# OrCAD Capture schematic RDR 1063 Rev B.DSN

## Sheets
1 6
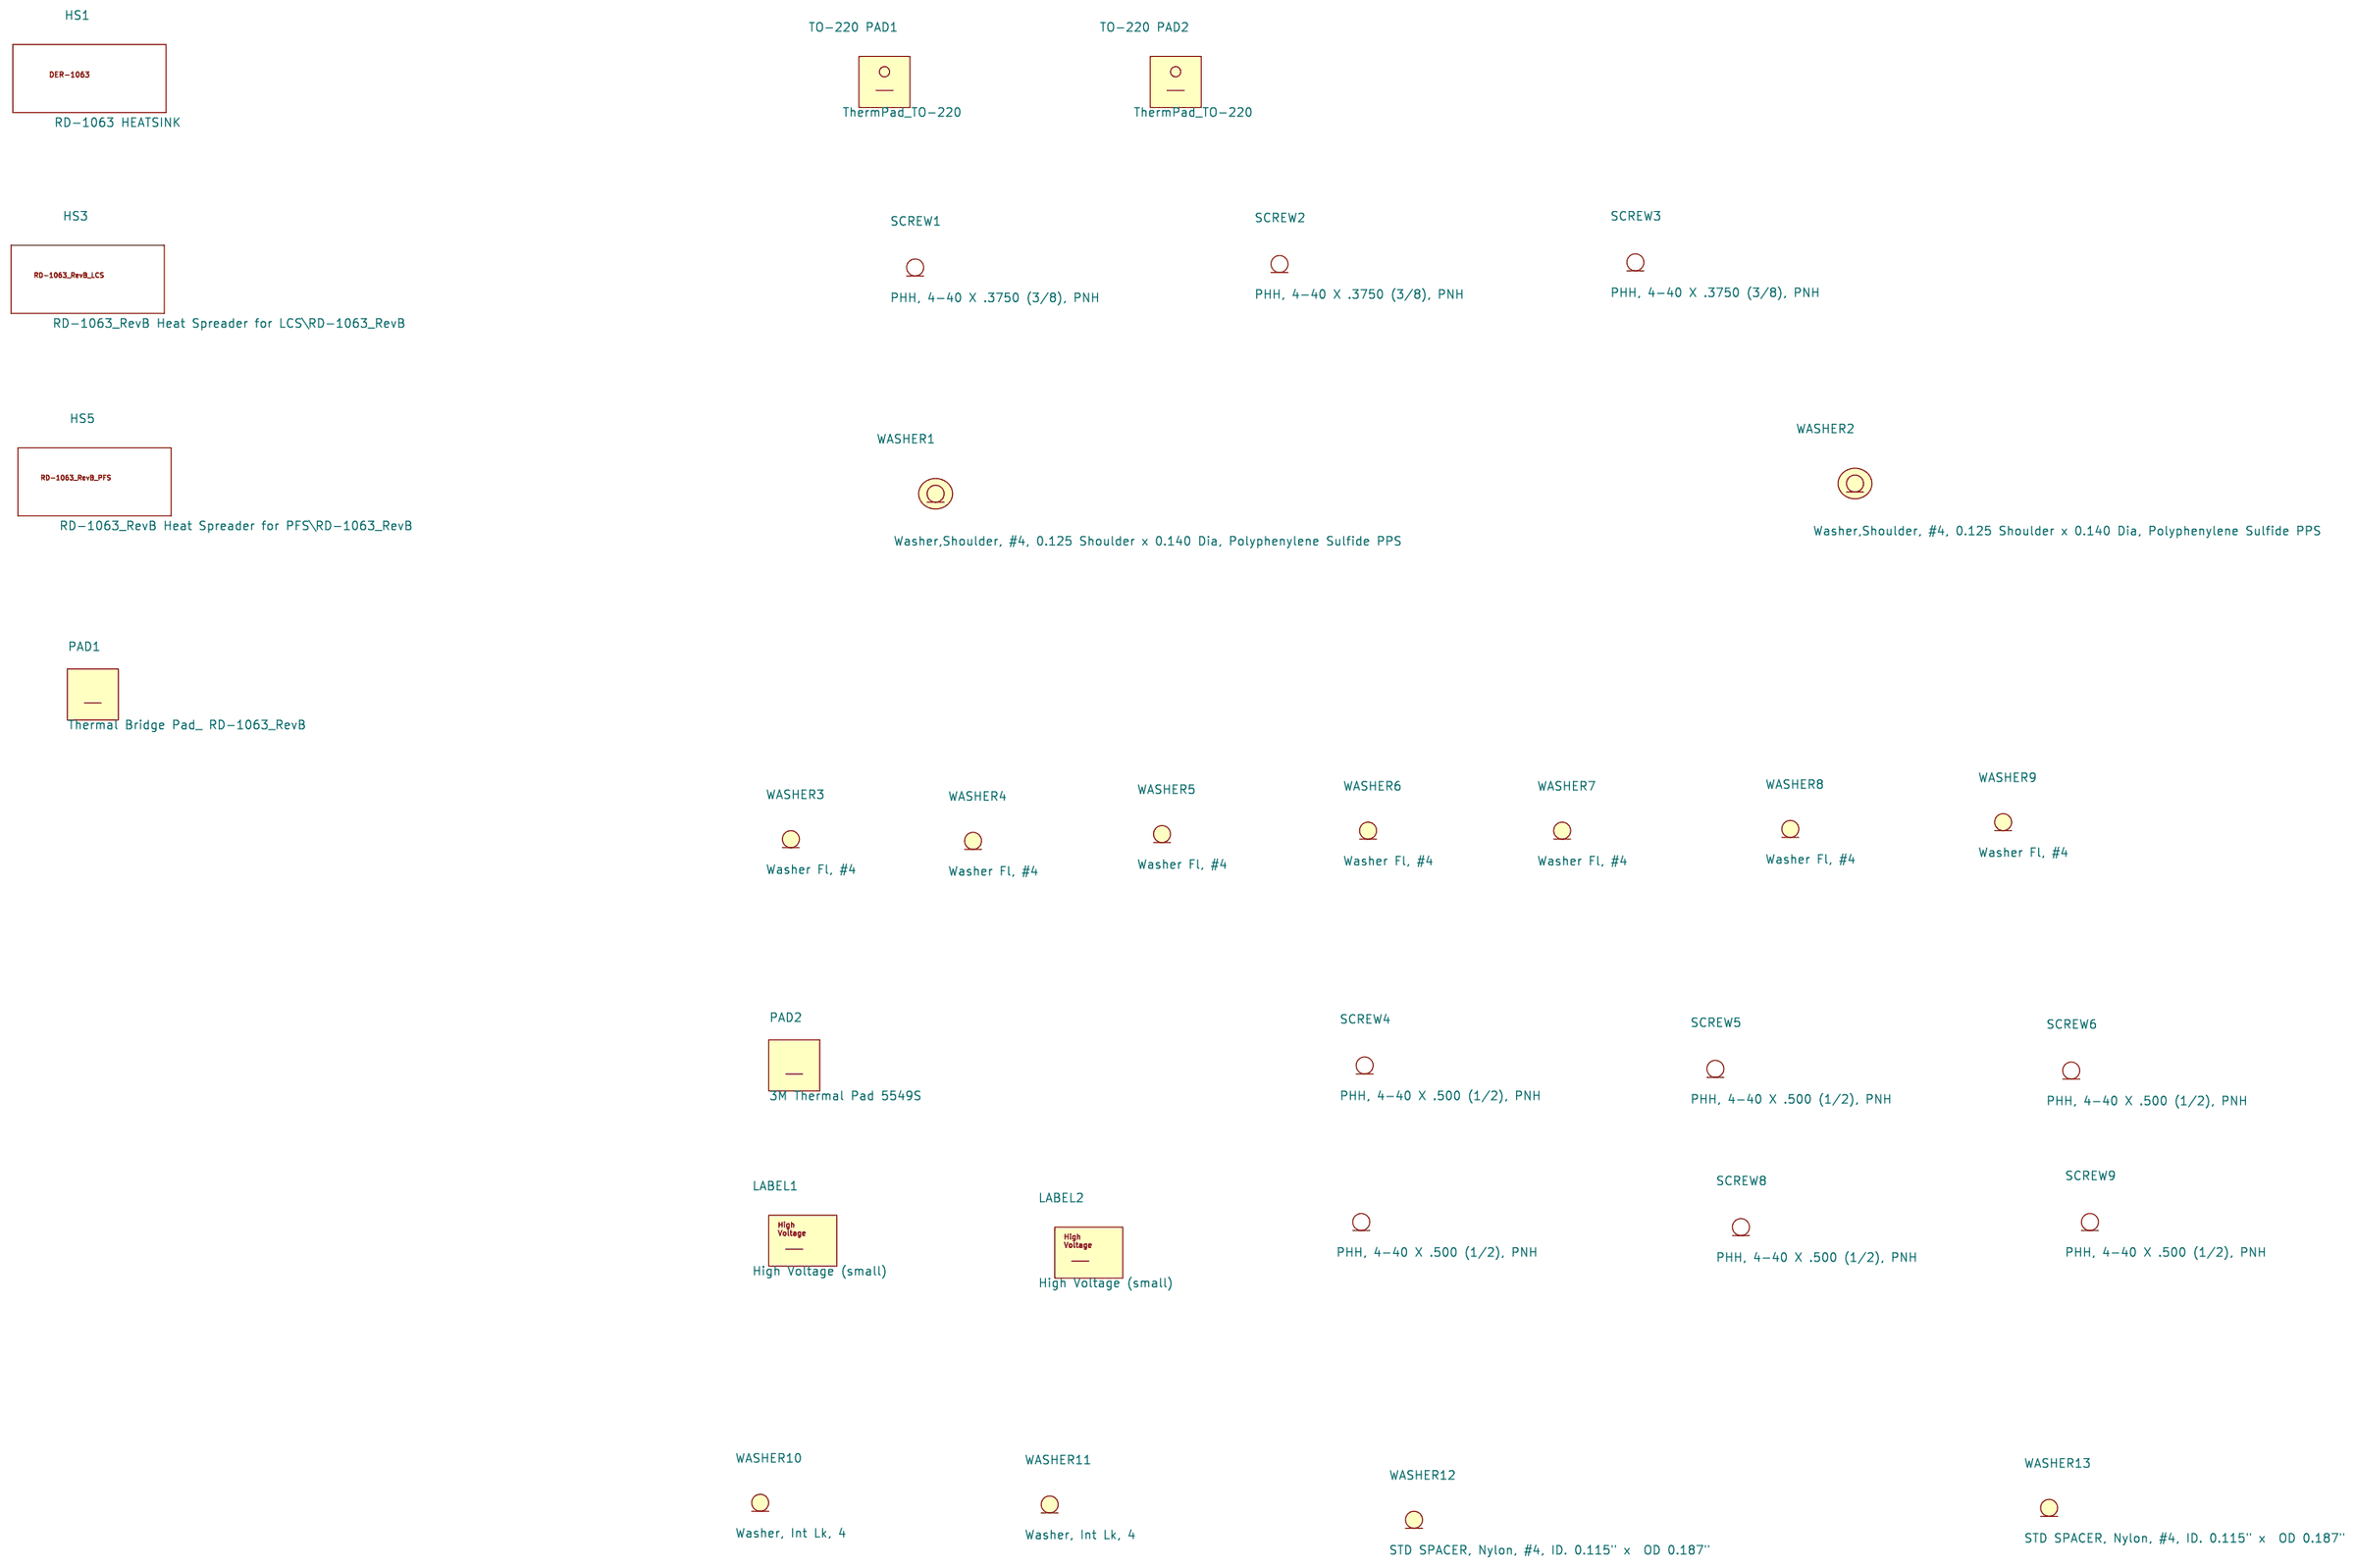
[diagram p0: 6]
2 5: size C; title: RDR-1063 720W, 60V 12A LCS; rev: A
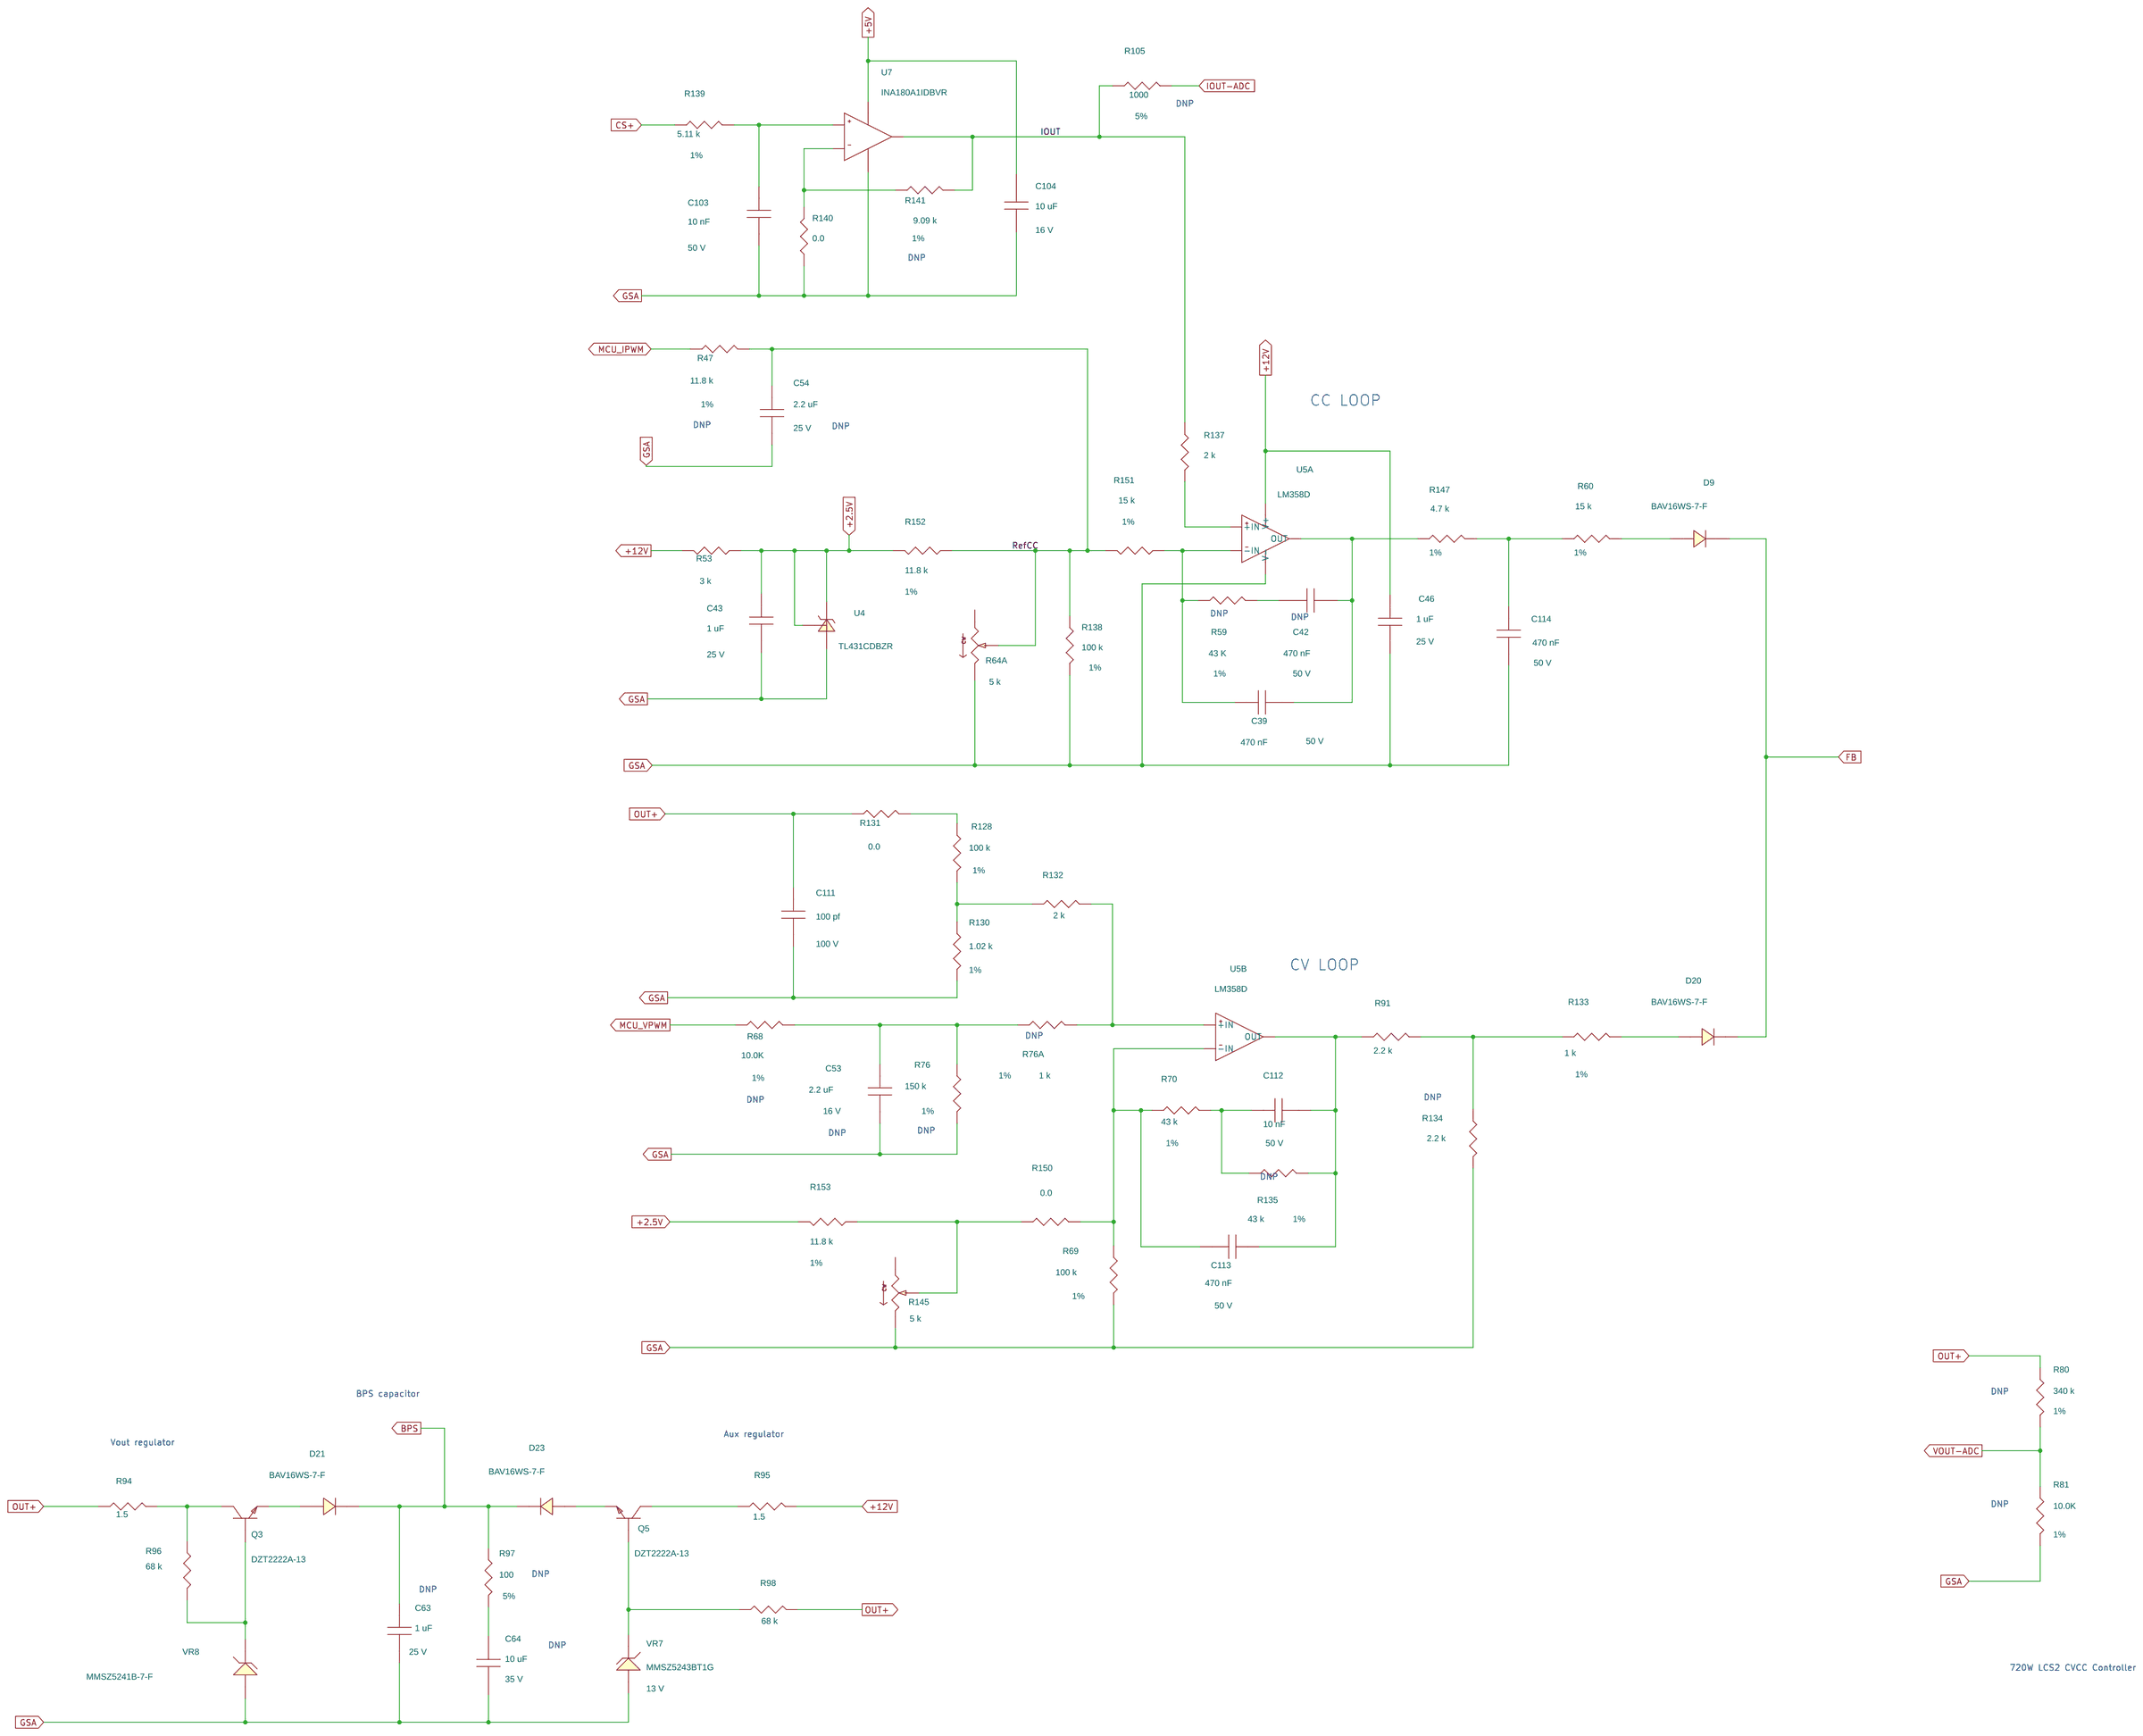
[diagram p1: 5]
3 4: size C; title: RDR-1063 720W, 60V 12A LCS; rev: A
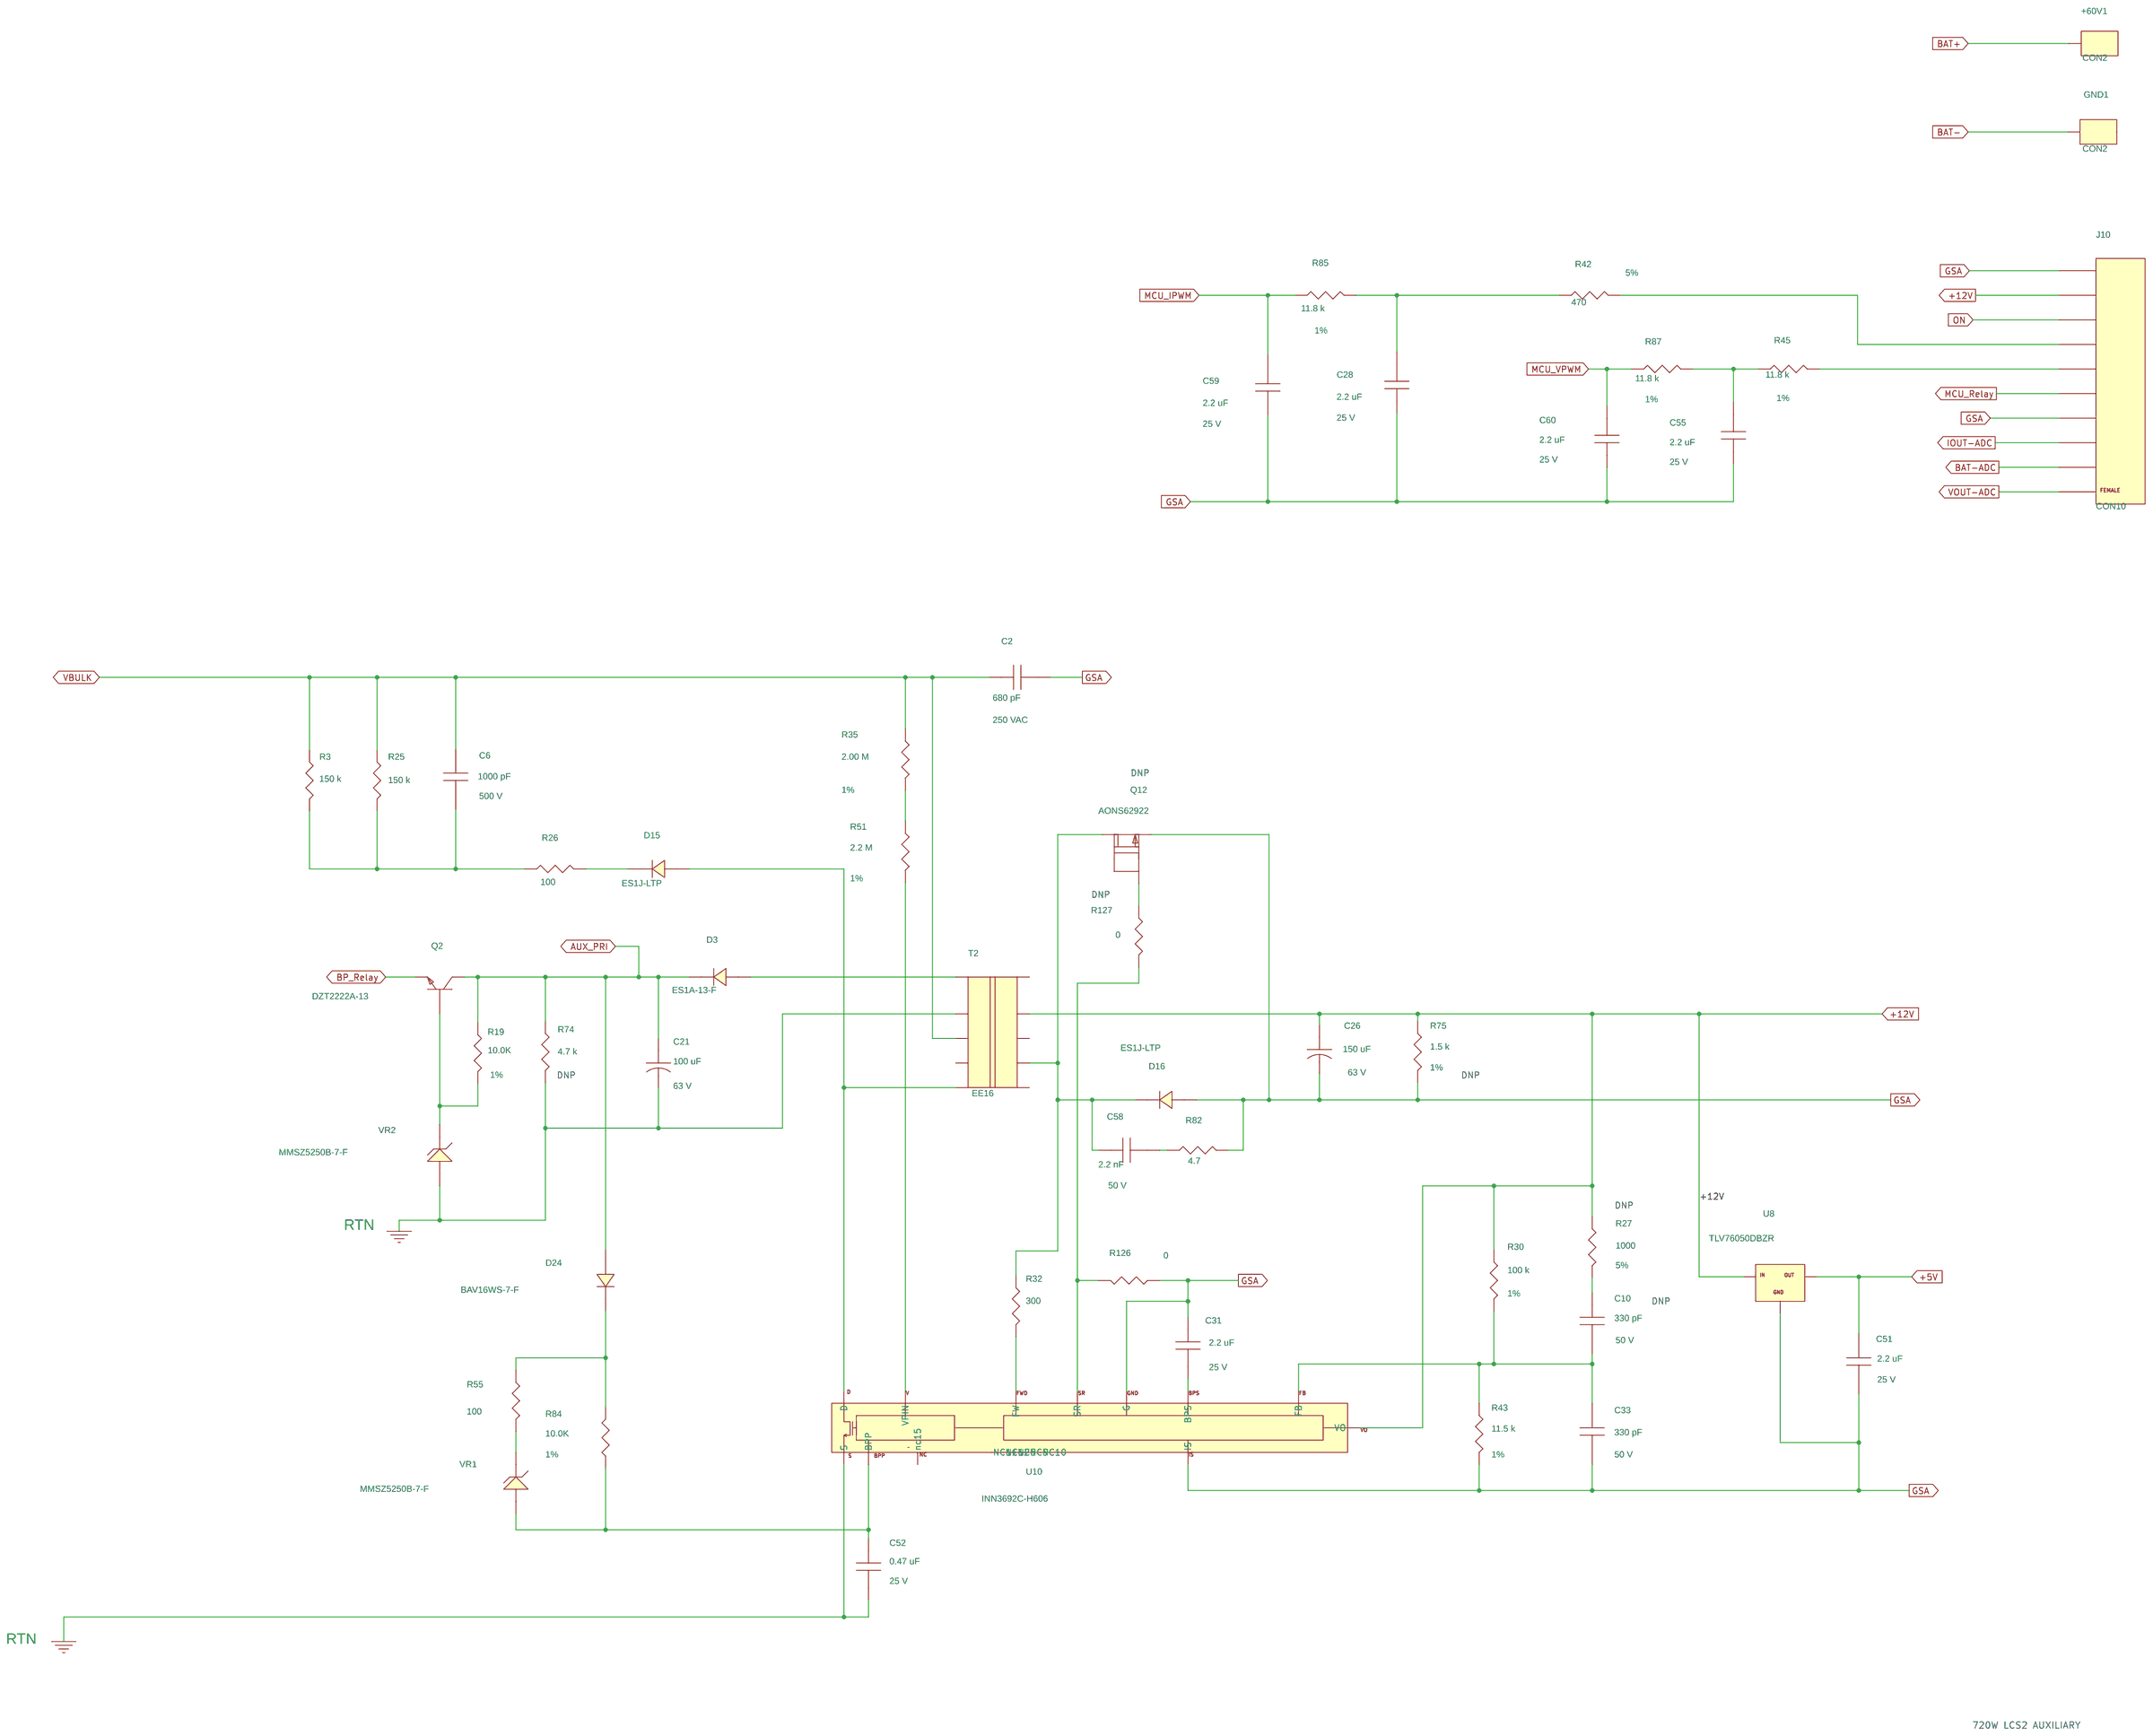
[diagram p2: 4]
4 3: size C; title: RDR-1063 720W, 60V 12A LCS; rev: A
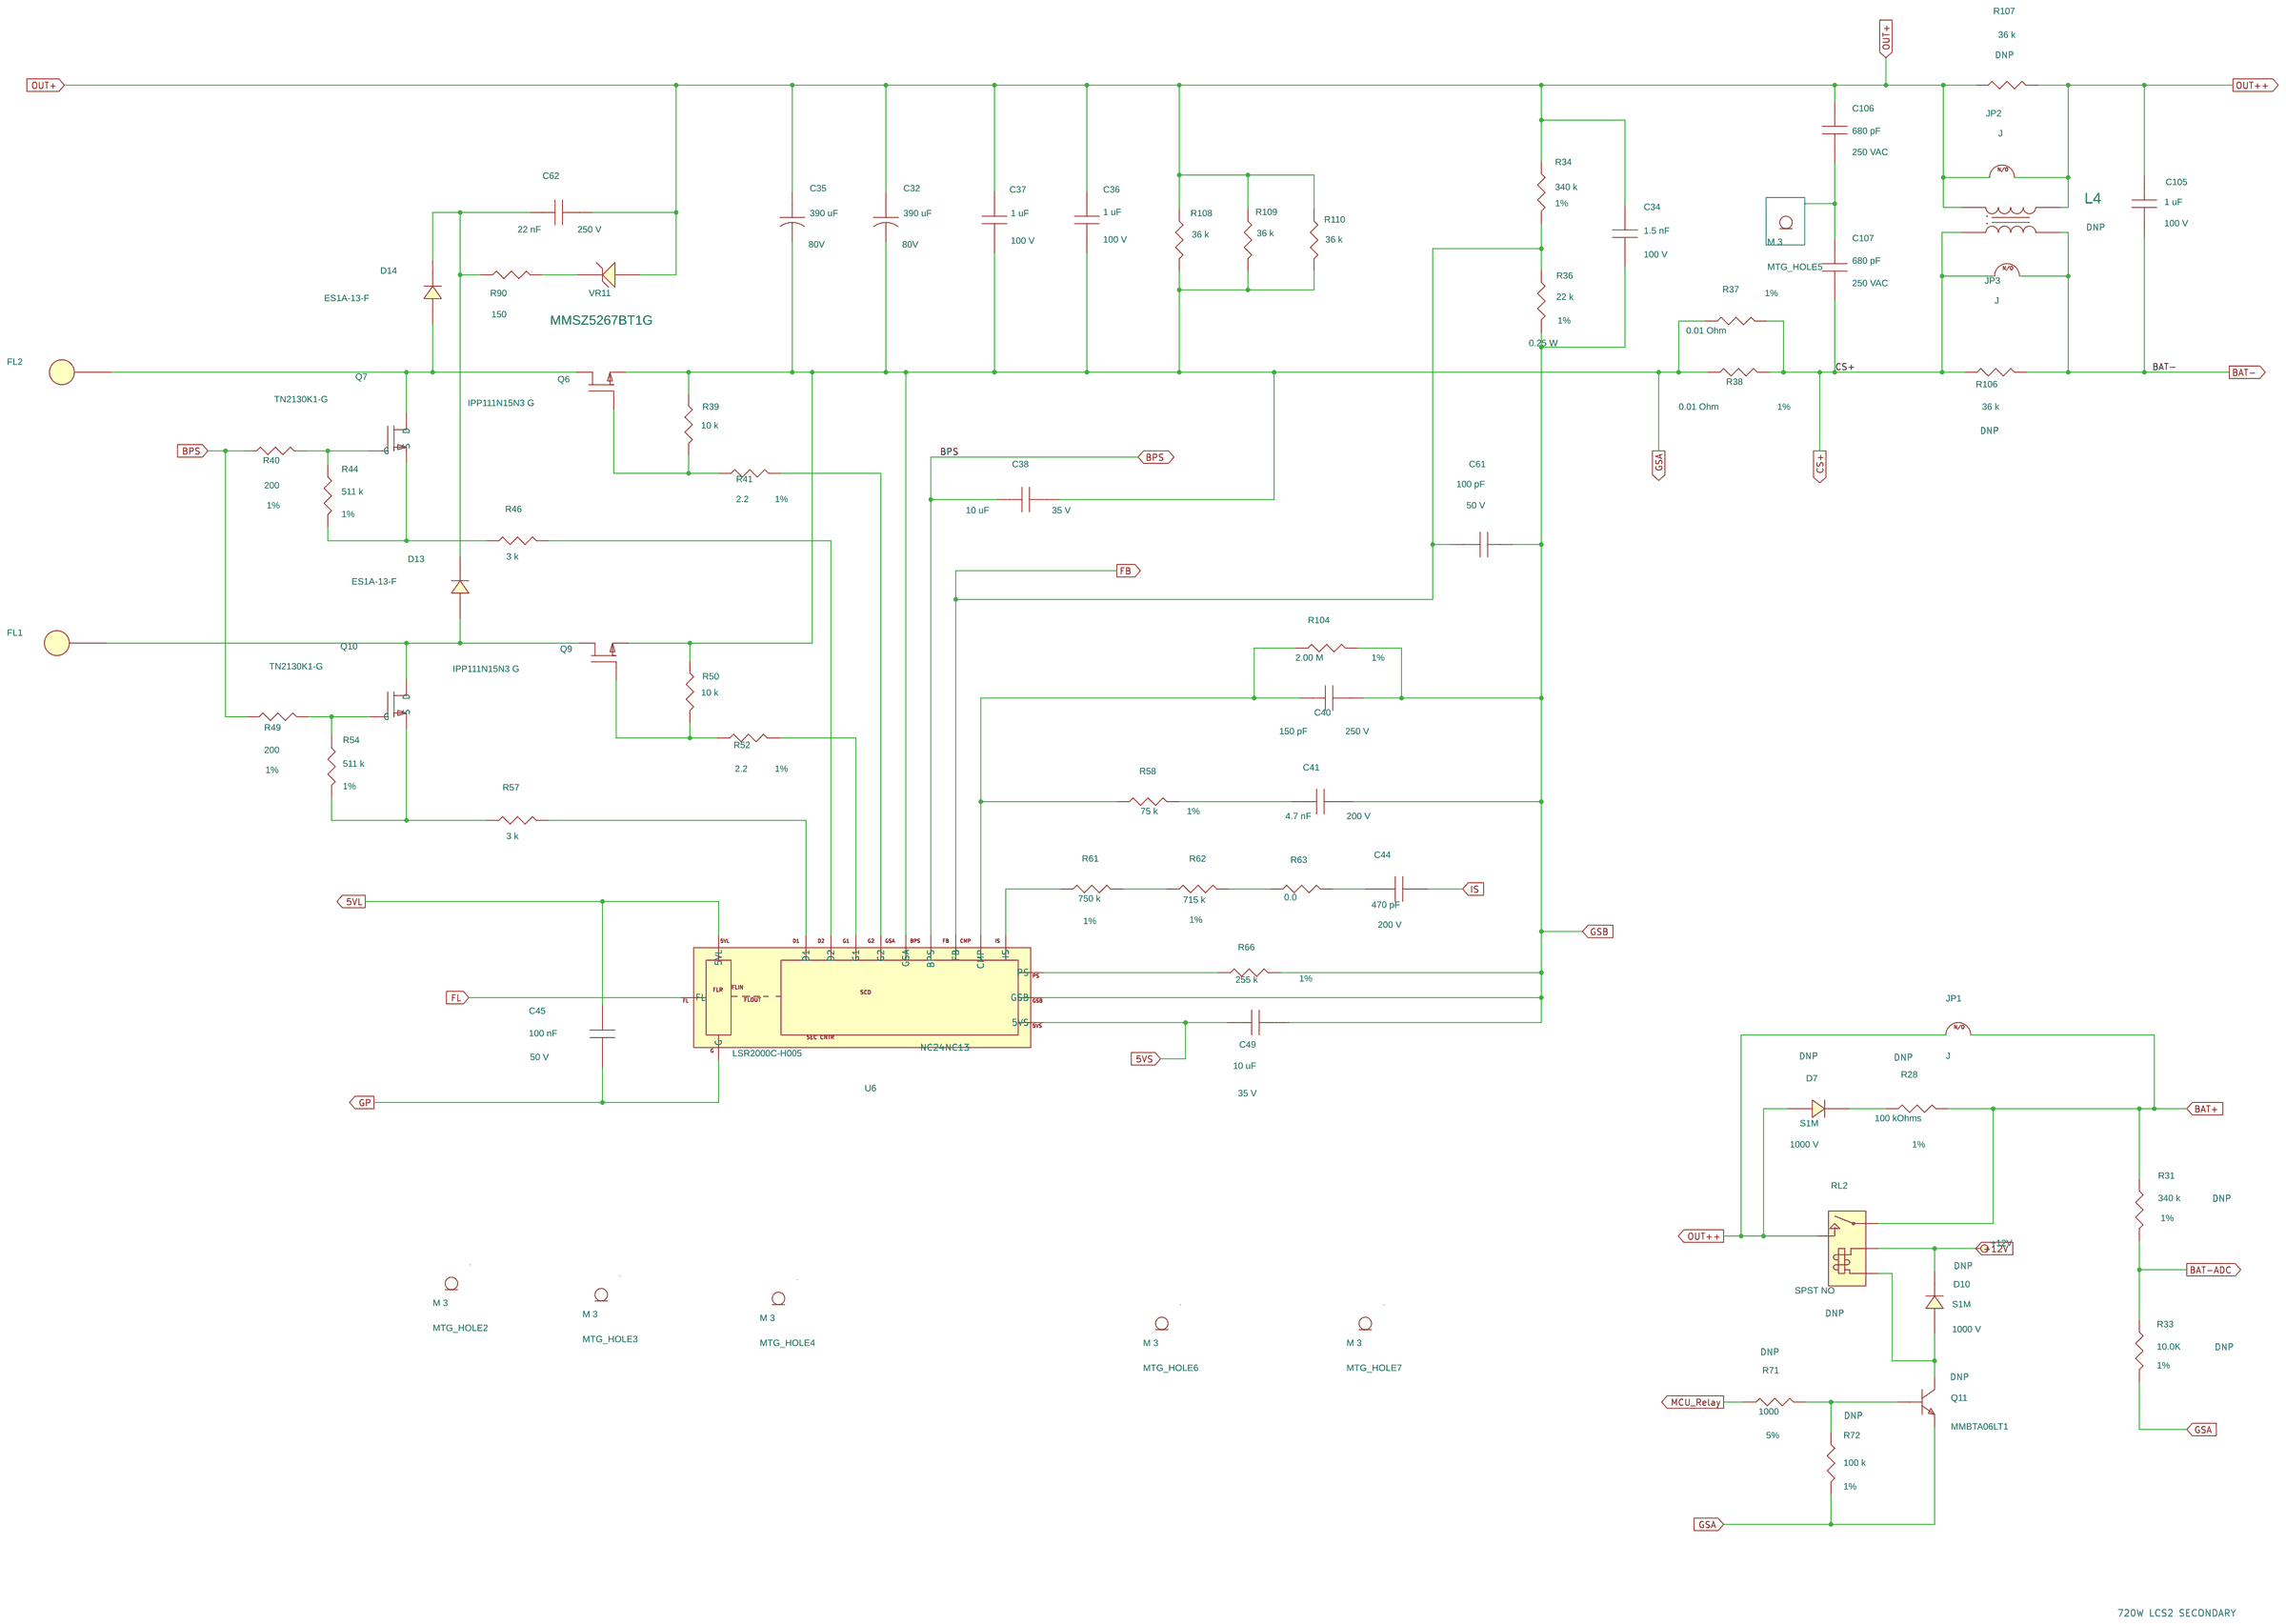
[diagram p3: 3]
5 2: size C; title: RDR-1063 720W, 60V 12A LCS; rev: A
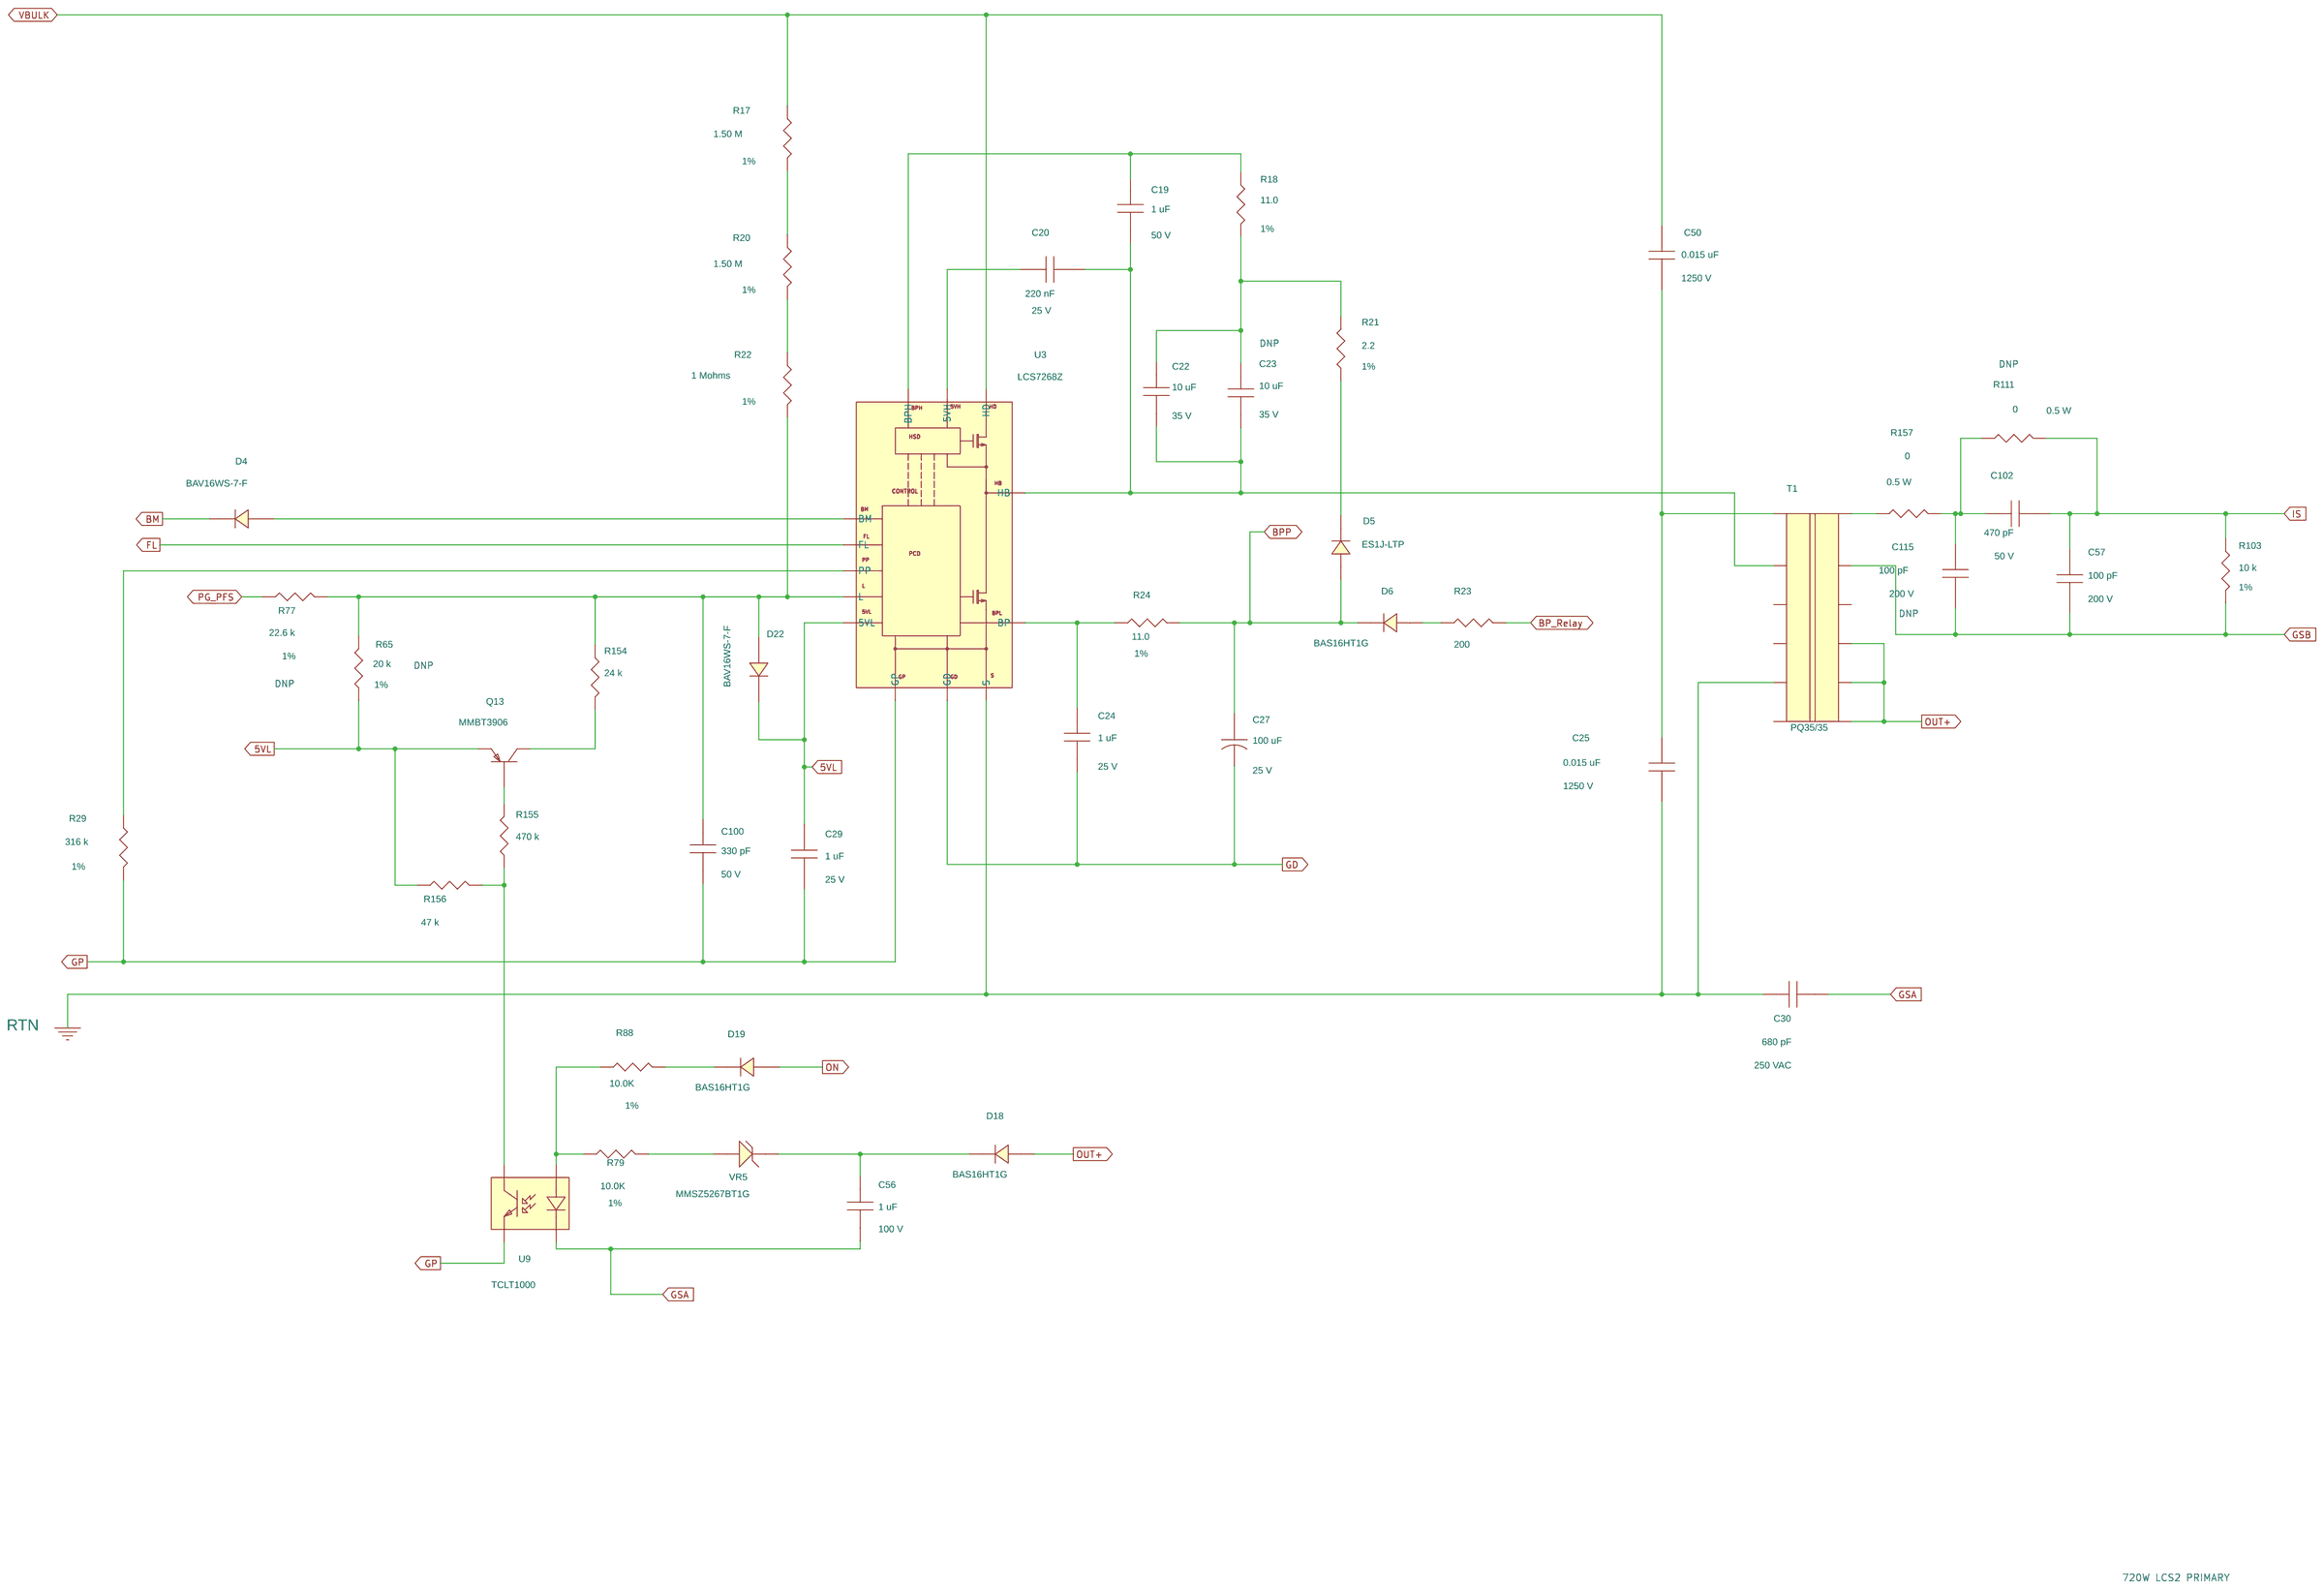
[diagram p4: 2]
6 1: size C; title: RDR-1063 720W, 60V 12A LCS; rev: A
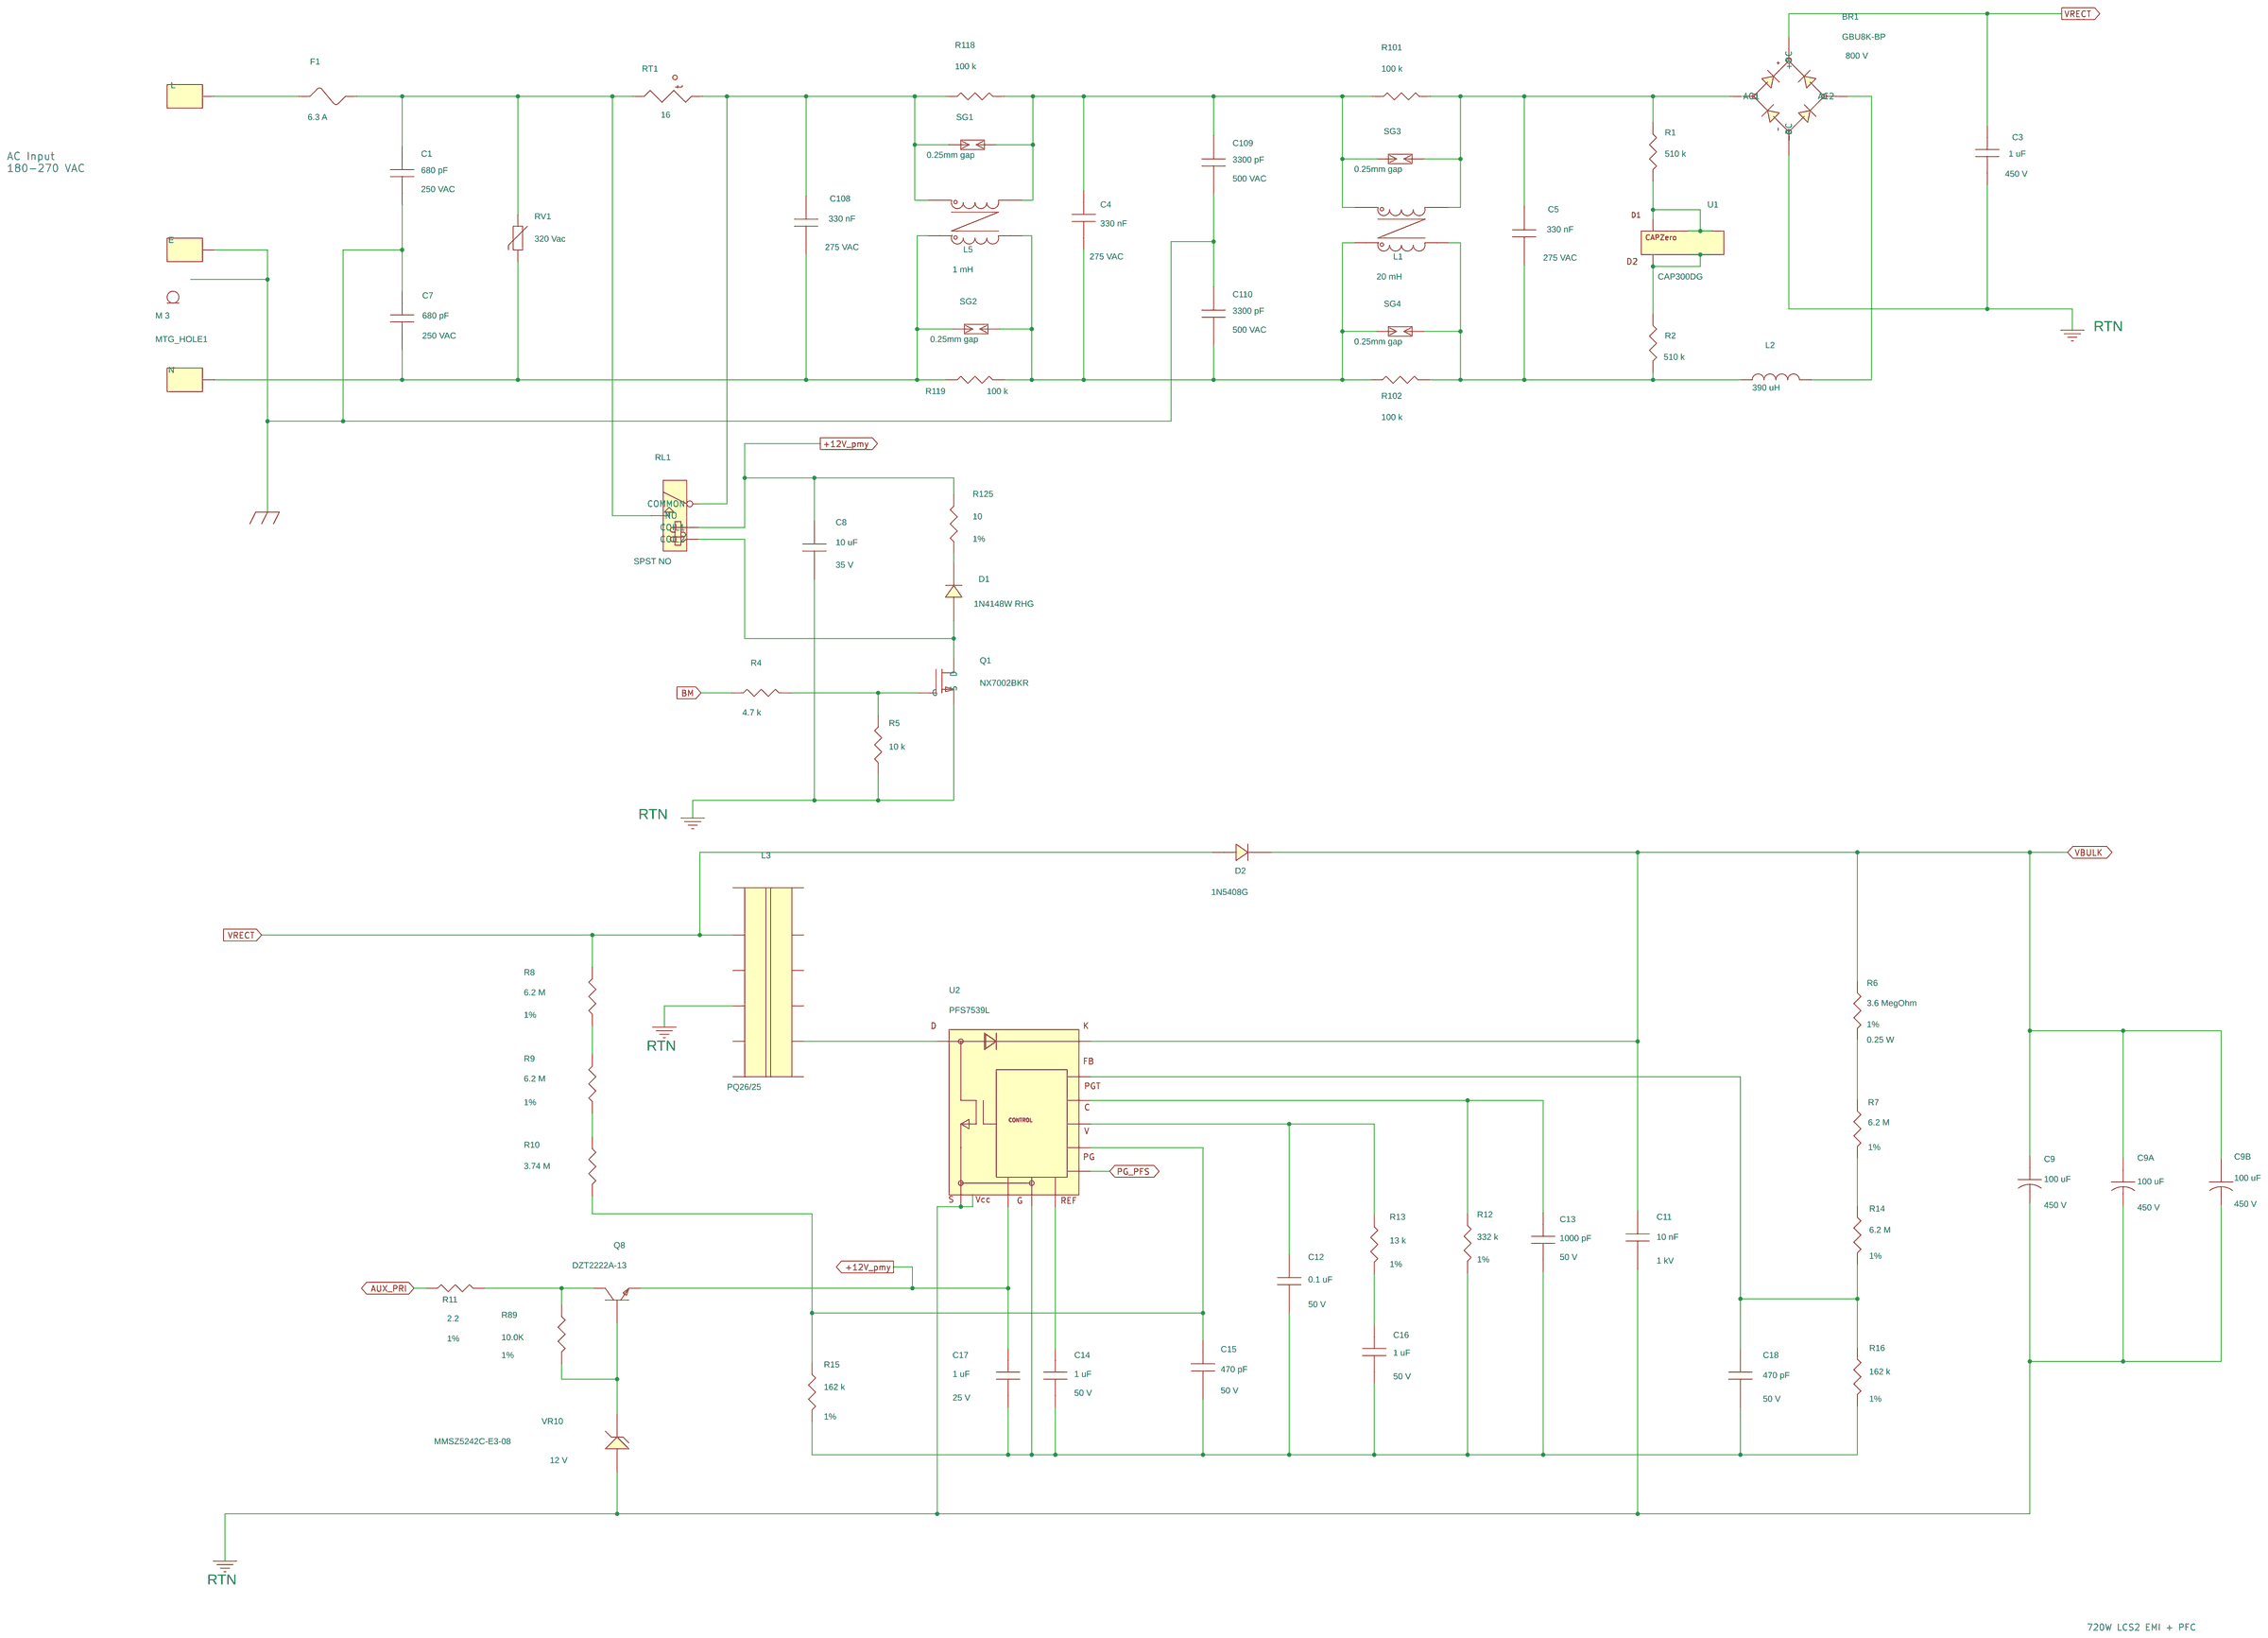
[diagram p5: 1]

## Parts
sheet 1
BR1  GBU8K-BP  [pidaxbridgegbu8]
C1  680 pF  [pinpycaprad470x210ls380040]
C3  1 uF  [pinpcaprad_12p6x9p2_ls10_d40]
C4  330 nF  [pi_np_710x355ls590d040]
C5  330 nF  [pi_np_710x355ls590d040]
C7  680 pF  [pinpycaprad470x210ls380040]
C8  10 uF  [pismc0805]
C9  100 uF  [pipolcapclyd16mmD040]
C9A  100 uF  [pipolcapclyd16mmD040]
C9B  100 uF  [pipolcapclyd16mmD040]
C11  10 nF  [pi_np_cap250x200ls170d030]
C12  0.1 uF  [pismc0603]
C13  1000 pF  [pismc0603]
C14  1 uF  [pismc0805]
C15  470 pF  [pismc0603]
C16  1 uF  [pismc0805]
C17  1 uF  [pismc0805]
C18  470 pF  [pismc0805]
C108  330 nF  [pi_np_710x355ls590d040]
C109  3300 pF  [pi_np11D5p5mmTd040]
C110  3300 pF  [pi_np11D5p5mmTd040]
D1  1N4148W RHG  [pi_sm_sod-123_12]
D2  1N5408G  [pidv300x200x060do15d0201ad]
E  CON2  [pi_conn_qc_tab_2pin_ls200]
F1  6.3 A  [PI_V_AX_BEL_0697H]
L  CON2  [pi_conn_qc_tab_2pin_ls200]
L1  20 mH  [der984_input_cmc]
L2  390 uH  [pitoroid2p650x1170ls560060]
L3  PQ26/25  [pibobbinpq262512p]
L5  1 mH  [pi_CMC_1mH]
MTG_HOLE1  M 3  [pimtgholem3]
N  CON2  [pi_conn_qc_tab_2pin_ls200]
Q1  NX7002BKR  [pismsot23123_1]
Q8  DZT2222A-13  [pismsot2231234]
R1  510 k  [pismr1206]
R2  510 k  [pismr1206]
R4  4.7 k  [pismr0805]
R5  10 k  [pismr0805]
R6  3.6 MegOhm  [pismr1206]
R7  6.2 M  [pismr1206]
R8  6.2 M  [pismr1206]
R9  6.2 M  [pismr1206]
R10  3.74 M  [pismr1206]
R11  2.2  [pismr0805]
R12  332 k  [pismr0603]
R13  13 k  [pismr0603]
R14  6.2 M  [pismr1206]
R15  162 k  [pismr0805]
R16  162 k  [pismr0805]
R89  10.0K  [pismr0603]
R101  100 k  [pismr0603]
R102  100 k  [pismr0603]
R118  100 k  [pismr0603]
R119  100 k  [pismr0603]
R125  10  [pismr0603]
RL1  SPST NO  [pi_relay_OJE]
RT1  16  [pirad800x250ls330052]
RV1  320 Vac  [pidisc610x212ls295x95040]
SG1  0.25mm gap  [PI_SPARK_GAP_0p25mm]
SG2  0.25mm gap  [PI_SPARK_GAP_0p25mm]
SG3  0.25mm gap  [PI_SPARK_GAP_0p25mm]
SG4  0.25mm gap  [PI_SPARK_GAP_0p25mm]
U1  CAP300DG  [pi_ic_smd_so8_capzero]
U2  PFS7539L  [piiclbendesiplg]
VR10  MMSZ5242C-E3-08  [pi_sm_sod-123_12]
sheet 2
C19  1 uF  [pismc0805]
C20  220 nF  [pismc0805]
C22  10 uF  [pismc1206]
C23  10 uF  [pismc1206]
C24  1 uF  [pismc0805]
C25  0.015 uF  [pinpxcaprad18x6mm040]
C27  100 uF  [pipolcapcyld250ls100030]
C29  1 uF  [pismc1206]
C30  680 pF  [pinpycaprad470x210ls380040]
C50  0.015 uF  [pinpxcaprad18x6mm040]
C56  1 uF  [pismc1206]
C57  100 pF  [pismc0805]
C100  330 pF  [pismc0603]
C102  470 pF  [pismc0805]
C115  100 pF  [pismc0805]
D4  BAV16WS-7-F  [pismsod323]
D5  ES1J-LTP  [pismdo214ac12]
D6  BAS16HT1G  [pismsod323]
D18  BAS16HT1G  [pismsod323]
D19  BAS16HT1G  [pismsod323]
D22  BAV16WS-7-F  [pismsod323]
Q13  MMBT3906  [pismsot23123_1]
R17  1.50 M  [pismr1206]
R18  11.0  [pismr0805]
R20  1.50 M  [pismr1206]
R21  2.2  [pismr0805]
R22  1 Mohms  [pismr1206]
R23  200  [pismr1206]
R24  11.0  [pismr0805]
R29  316 k  [pismr0603]
R65  20 k  [pismr0603]
R77  22.6 k  [pismr0603]
R79  10.0K  [pismr0603]
R88  10.0K  [pismr0603]
R103  10 k  [pismr0805]
R111  0  [pismr0805]
R154  24 k  [pismr0603]
R155  470 k  [pismr0603]
R156  47 k  [pismr0603]
R157  0  [pismr0805]
T1  PQ35/35  [pi_bobbin_bpq35_35_12p]
U3  LCS7268Z  [pi_PoweDIP_B18pAUNP]
U9  TCLT1000  [PISM-4DIP-SLM-1]
VR5  MMSZ5267BT1G  [pi_sm_sod-123_12]
sheet 3
C32  390 uF  [pipolcapclyd500ls200040]
C34  1.5 nF  [pismc1206]
C35  390 uF  [pipolcapclyd500ls200040]
C36  1 uF  [pismc1206]
C37  1 uF  [pismc1206]
C38  10 uF  [pismc1206]
C40  150 pF  [pismc0603]
C41  4.7 nF  [pismc0805]
C44  470 pF  [pismc0603]
C45  100 nF  [pismc0805]
C49  10 uF  [pismc0805]
C61  100 pF  [pismc0603]
C62  22 nF  [pismc0805]
C105  1 uF  [pismc1206]
C106  680 pF  [pinpycaprad470x210ls380040]
C107  680 pF  [pinpycaprad470x210ls380040]
D7  S1M  [pismdsma]
D10  S1M  [pismdsma]
D13  ES1A-13-F  [pismdo214ac12]
D14  ES1A-13-F  [pismdo214ac12]
FL1  Hole_156mils  [pi_hole_156mil]
FL2  Hole_156mils  [pi_hole_156mil]
JP1  J  [pi_jumper500-16awg-sld]
JP2  J  [pi_jumper200-16awg-sld]
JP3  J  [pi_jumper200-16awg-sld]
L4  1mH  [WE-CMBNC_Type_S]
MTG_HOLE2  M 3  [pimtgholem3p15mmUNP]
MTG_HOLE3  M 3  [pimtgholem3p15mmUNP]
MTG_HOLE4  M 3  [pimtgholem3p15mmUNP]
MTG_HOLE5  M 3  [pimtgholem3]
MTG_HOLE6  M 3  [pimtgholem3]
MTG_HOLE7  M 3  [pimtgholem3]
Q6  IPP111N15N3 G  [PITO220ABVF1]
Q7  TN2130K1-G  [pismsot23123_1]
Q9  IPP111N15N3 G  [PITO220ABVF1]
Q10  TN2130K1-G  [pismsot23123_1]
Q11  MMBTA06LT1  [pismsot23123_1]
R28  100 kOhms  [pismr2512]
R31  340 k  [pismr0603]
R33  10.0K  [pismr0603]
R34  340 k  [pismr0603]
R36  22 k  [pismr0603]
R37  0.01 Ohm  [pismr2512]
R38  0.01 Ohm  [pismr2512]
R39  10 k  [pismr0805]
R40  200  [pismr0603]
R41  2.2  [pismr0603]
R44  511 k  [pismr0603]
R46  3 k  [pismr0805]
R49  200  [pismr0603]
R50  10 k  [pismr0805]
R52  2.2  [pismr0603]
R54  511 k  [pismr0603]
R57  3 k  [pismr0805]
R58  75 k  [pismr1206]
R61  750 k  [pismr0603]
R62  715 k  [pismr0603]
R63  0.0  [pismr0603]
R66  255 k  [pismr0603]
R71  1000  [pismr0603]
R72  100 k  [pismr0603]
R90  150  [pismr1206]
R104  2.00 M  [pismr0603]
R106  36 k  [pismr1206]
R107  36 k  [pismr1206]
R108  36 k  [pismr1206]
R109  36 k  [pismr1206]
R110  36 k  [pismr1206]
RL2  SPST NO  [pi_relay_SongChuan895_4pin]
U6  LSR2000C-H005  [pi_ic_insop_24D]
VR11  MMSZ5267BT1G  [pi_sm_sod-123_12]
sheet 4
+60V1  CON2  [pi_conn_qc_tab_2pin_ls200]
C2  680 pF  [pinpycaprad470x210ls380040]
C6  1000 pF  [pismc1206]
C10  330 pF  [pismc0603]
C21  100 uF  [pipolcapclyd320ls140030]
C26  150 uF  [pipolcapclyd320ls140030]
C28  2.2 uF  [pismc0603]
C31  2.2 uF  [pismc1206]
C33  330 pF  [pismc0603]
C51  2.2 uF  [pismc0805]
C52  0.47 uF  [pismc0805]
C55  2.2 uF  [pismc0603]
C58  2.2 nF  [pismc0603]
C59  2.2 uF  [pismc0603]
C60  2.2 uF  [pismc0603]
D3  ES1A-13-F  [pismdo214ac12]
D15  ES1J-LTP  [pismdo214ac12]
D16  ES1J-LTP  [pismdo214ac12]
D24  BAV16WS-7-F  [pismsod323]
GND1  CON2  [pi_conn_qc_tab_2pin_ls200]
J10  CON10  [PI_HDRF_1X10_Sullins]
Q2  DZT2222A-13  [pismsot2231234]
Q12  AONS62922  [pismpqfn5x6b]
R3  150 k  [pismr1206]
R19  10.0K  [pismr0603]
R25  150 k  [pismr1206]
R26  100  [pismr1206]
R27  1000  [pismr0603]
R30  100 k  [pismr0603]
R32  300  [pismr0603]
R35  2.00 M  [pismr1206]
R42  470  [pismr0603]
R43  11.5 k  [pismr0603]
R45  11.8 k  [pismr0603]
R51  2.2 M  [pismr1206]
R55  100  [pismr0603]
R74  4.7 k  [pismr1206]
R75  1.5 k  [pismr1206]
R82  4.7  [pismr0603]
R84  10.0K  [pismr0603]
R85  11.8 k  [pismr0603]
R87  11.8 k  [pismr0603]
R126  0  [pismr0603]
R127  0  [pismr0603]
T2  EE16  [pi_bobbin_ee16_10p_yw-527-00b]
U8  TLV76050DBZR  [pismsot23132]
U10  INN3692C-H606  [pi_ic_insop_24d]
VR1  MMSZ5250B-7-F  [pi_sm_sod-123_12]
VR2  MMSZ5250B-7-F  [pi_sm_sod-123_12]
sheet 5
C39  470 nF  [pismc0603]
C42  470 nF  [pismc0805]
C43  1 uF  [pismc0603]
C46  1 uF  [pismc0603]
C53  2.2 uF  [pismc0603]
C54  2.2 uF  [pismc0603]
C63  1 uF  [pismc1206]
C64  10 uF  [pismc1206]
C103  10 nF  [pismc0805]
C104  10 uF  [pismc0805]
C111  100 pf  [pismc0805]
C112  10 nF  [pismc0603]
C113  470 nF  [pismc0603]
C114  470 nF  [pismc0603]
D9  BAV16WS-7-F  [pismsod323]
D20  BAV16WS-7-F  [pismsod323]
D21  BAV16WS-7-F  [pismsod323]
D23  BAV16WS-7-F  [pismsod323]
Q3  DZT2222A-13  [pismsot2231234]
Q5  DZT2222A-13  [pismsot2231234]
R47  11.8 k  [pismr0603]
R53  3 k  [pismr0603]
R59  43 K  [pismr0805]
R60  15 k  [pismr0603]
R64A  5 k  [pivres9mmsquare]
R68  10.0K  [pismr0603]
R69  100 k  [pismr0805]
R70  43 k  [pismr0603]
R76  150 k  [pismr0603]
R76A  1 k  [pismr0603]
R80  340 k  [pismr0603]
R81  10.0K  [pismr0603]
R91  2.2 k  [pismr0805]
R94  1.5  [pismr0805]
R95  1.5  [pismr0805]
R96  68 k  [pismr0603]
R97  100  [pismr0805]
R98  68 k  [pismr0603]
R105  1000  [pismr0603]
R128  100 k  [pismr0603]
R130  1.02 k  [pismr0603]
R131  0.0  [pismr0603]
R132  2 k  [pismr0603]
R133  1 k  [pismr0603]
R134  2.2 k  [pismr0603]
R135  43 k  [pismr0603]
R137  2 k  [pismr0603]
R138  100 k  [pismr0603]
R139  5.11 k  [pismr0603]
R140  0.0  [pismr0603]
R141  9.09 k  [pismr0603]
R145  5 k  [pivres9mmsquare]
R147  4.7 k  [pismr0603]
R150  0.0  [pismr0603]
R151  15 k  [pismr0603]
R152  11.8 k  [pismr0603]
R153  11.8 k  [pismr0603]
U4  TL431CDBZR  [pismsot23123_1]
U5  LM358D  [pismso8]  (sections A,B)
U7  INA180A1IDBVR  [pismsot235]
VR7  MMSZ5243BT1G  [pi_sm_sod-123_12]
VR8  MMSZ5241B-7-F  [pi_sm_sod-123_12]
sheet 6
HS1  RD-1063 HEATSINK  [PI_hs_0p_RD-1063]
HS3  RD-1063_RevB Heat Spreader for LCS\RD-1063_RevB  [PI_hs_0p_RD-1063_RevB_LCS]
HS5  RD-1063_RevB Heat Spreader for PFS\RD-1063_RevB  [PI_hs_0p_RD-1063_RevB_PFS]
LABEL1  High Voltage (small)
LABEL2  High Voltage (small)
PAD1  Thermal Bridge Pad_ RD-1063_RevB
PAD2  3M Thermal Pad 5549S
SCREW1  PHH, 4-40 X .3750 (3/8), PNH
SCREW2  PHH, 4-40 X .3750 (3/8), PNH
SCREW3  PHH, 4-40 X .3750 (3/8), PNH
SCREW4  PHH, 4-40 X .500 (1/2), PNH
SCREW5  PHH, 4-40 X .500 (1/2), PNH
SCREW6  PHH, 4-40 X .500 (1/2), PNH
SCREW7  PHH, 4-40 X .500 (1/2), PNH
SCREW8  PHH, 4-40 X .500 (1/2), PNH
SCREW9  PHH, 4-40 X .500 (1/2), PNH
TO-220 PAD1  ThermPad_TO-220
TO-220 PAD2  ThermPad_TO-220
WASHER1  Washer,Shoulder, #4, 0.125 Shoulder x 0.140 Dia, Polyphenylene Sulfide PPS
WASHER2  Washer,Shoulder, #4, 0.125 Shoulder x 0.140 Dia, Polyphenylene Sulfide PPS
WASHER3  Washer Fl, #4
WASHER4  Washer Fl, #4
WASHER5  Washer Fl, #4
WASHER6  Washer Fl, #4
WASHER7  Washer Fl, #4
WASHER8  Washer Fl, #4
WASHER9  Washer Fl, #4
WASHER10  Washer, Int Lk, 4
WASHER11  Washer, Int Lk, 4
WASHER12  STD SPACER, Nylon, #4, ID. 0.115" x  OD 0.187"
WASHER13  STD SPACER, Nylon, #4, ID. 0.115" x  OD 0.187"

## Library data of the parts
BR1 = DISCRETE_BRIDGE_+~~-: ALT_SYMBOLS: pidaxbridgegbu8_horz; Disp_Voltage: 800 V; FPLIST: pidaxbridgegbu8,pidaxbridgegbu8_horz; Part Number: 15-00347-00
C1 C2 C7 C30 C106 C107 = CAP_NP: Disp_Voltage: 250 VAC; Part Number: 20-00374-00; Voltage: 250 VAC
C3 = CAP_NP: ALT_SYMBOLS: pinpcaprad_12p6x9p2_ls10_d400H; Disp_Voltage: 450 V; FPLIST: pinpcaprad_12p6x9p2_ls10_d40,pinpcaprad_12p6x9p2_ls10_d40H; Part Number: 20-09184-00; Voltage: 450 V
C4 C5 C108 = CAP_NP: Disp_Voltage: 275 VAC; Part Number: 20-08576-00; Voltage: 275 VAC
C8 C49 = CAP_NP: ALT_SYMBOLS: Unisem_RMCF0805UL,CC0805,pismc0805_1; Disp_Voltage: 35 V; FPLIST: pismc0805,Unisem_RMCF0805UL,CC0805,pismc0805_1; Part Number: 20-01692-00; Voltage: 35 V
C9 C9A C9B = CAP_POL: ALT_SYMBOLS: pipolcapclyd16x37mmD040H; Disp_Voltage: 450 V; FPLIST: pipolcapclyd16mmD040,pipolcapclyd16x37mmD040H; Part Number: 20-01649-00; Voltage: 450 V
C11 = CAP_NP: Disp_Voltage: 1 kV; Part Number: 20-00894-00; Voltage: 1 kV
C12 = CAP_NP: ALT_SYMBOLS: Unisem_RMCF0603UL; Disp_Voltage: 50 V; FPLIST: pismc0603,Unisem_RMCF0603UL; Part Number: 20-02295-00; Voltage: 50 V
C13 = CAP_NP: ALT_SYMBOLS: Unisem_RMCF0603UL; Disp_Voltage: 50 V; FPLIST: pismc0603,Unisem_RMCF0603UL; Part Number: 20-09119-00; Voltage: 50 V
C14 C16 C19 = CAP_NP: ALT_SYMBOLS: Unisem_RMCF0805UL; Disp_Voltage: 50 V; FPLIST: pismc0805,Unisem_RMCF0805UL; Part Number: 20-02193-00; Voltage: 50 V
C15 = CAP_NP: ALT_SYMBOLS: Unisem_RMCF0603UL; Disp_Voltage: 50 V; FPLIST: pismc0603,Unisem_RMCF0603UL; Part Number: 20-09118-00; Voltage: 50 V
C17 C24 = CAP_NP: ALT_SYMBOLS: Unisem_RMCF0805UL; Disp_Voltage: 25 V; FPLIST: pismc0805,Unisem_RMCF0805UL; Part Number: 20-09171-00; Voltage: 25 V
C18 C102 = CAP_NP: ALT_SYMBOLS: Unisem_RMCF0805UL; Disp_Voltage: 50 V; FPLIST: pismc0805,Unisem_RMCF0805UL; Part Number: 20-00205-00; Voltage: 50 V
C109 C110 = CAP_NP: Disp_Voltage: 500 VAC; Part Number: 20-09131-00; Voltage: 500 VAC
D1 = DIODE: ALT_SYMBOLS: pi_sm_sod-123_12_1; FPLIST: pi_sm_sod-123_12,pi_sm_sod-123_12_1; Part Number: 15-01269-00
D2 = DIODE: ALT_SYMBOLS: pidv300x472x060do14wbead,pidax800x225060do15do201ad,pidv300x200x060do14wbead; FPLIST: pidv300x200x060do15d0201ad,pidv300x472x060do14wbead,pidax800x225060do15do201ad,pidv300x200x060do14wbead; Part Number: 15-01651-00
E = CON1_2P_TAB_1: Part Number: 35-00281-00
F1 = FUSE: ALT_SYMBOLS: PI_V_AX_BEL_0697H_H; FPLIST: PI_V_AX_BEL_0697H,PI_V_AX_BEL_0697H_H; Part Number: 40-00089-00
L = CON1_2P_TAB_0: Part Number: 35-00281-00
L1 = TORRID_4P_14_23: Part Number: 30-00636-00
L2 = INDUCTOR: Part Number: 32-00190-00
L3 = BPQ26_25_12P_GENERIC: Part Number: 25-00055-00
L5 = TORRID_4P_14_23: Part Number: 32-00448-00
MTG_HOLE1-MTG_HOLE7 = MTG_HOLE_M3: FPLIST: pimtgholem3p15mmUNP,pimtgholem3; Part Number: 66-00005-00
N = CON1_2P_TAB_2: Part Number: 35-00281-00
Q1 = FET_N_GSD: Part Number: 50-00261-00
Q2 Q3 Q5 Q8 = NPN_BCEC: Part Number: 55-00198-00
R1 R2 = R: Part Number: 05-01417-00
R4 = R: ALT_SYMBOLS: Unisem_RMCF0805UL; FPLIST: pismr0805,Unisem_RMCF0805UL; Origin: Altium; Part Number: 05-01535-00
R5 R39 R50 = R: ALT_SYMBOLS: Unisem_RMCF0805UL; FPLIST: pismr0805,Unisem_RMCF0805UL; Part Number: 05-01543-00
R6 = R: Disp_Power: 0.25 W; Disp_Tol: 1%; Part Number: 05-07648-00
R7-R9 R14 = R: Disp_Tol: 1%; Part Number: 05-05567-00
R10 = R: Part Number: 05-05572-00
R11 R21 = R: ALT_SYMBOLS: Unisem_RMCF0805UL; Disp_Tol: 1%; FPLIST: pismr0805,Unisem_RMCF0805UL; Part Number: 05-06397-00
R12 = R: ALT_SYMBOLS: Unisem_RMCF0603UL; Disp_Tol: 1%; FPLIST: pismr0603,Unisem_RMCF0603UL; Part Number: 05-01224-00
R13 = R: ALT_SYMBOLS: Unisem_RMCF0603UL; Disp_Tol: 1%; FPLIST: pismr0603,Unisem_RMCF0603UL; Part Number: 05-03193-00
R15 R16 = R: ALT_SYMBOLS: Unisem_RMCF0805UL; Disp_Tol: 1%; FPLIST: pismr0805,Unisem_RMCF0805UL; Part Number: 05-00800-00
R19 R33 R68 R79 R81 R84 R88 R89 = R: ALT_SYMBOLS: Unisem_RMCF0603UL; Disp_Tol: 1%; FPLIST: pismr0603,Unisem_RMCF0603UL; Part Number: 05-06492-00
R101 R102 R118 R119 = R: ALT_SYMBOLS: Unisem_RMCF0603UL; FPLIST: pismr0603,Unisem_RMCF0603UL; Part Number: 05-01736-00
R125 = R: ALT_SYMBOLS: Unisem_RMCF0603UL; Disp_Tol: 1%; FPLIST: pismr0603,Unisem_RMCF0603UL; Part Number: 05-03548-00
RL1 = RELAY_SPST_NO_OMRON-G6RL: Part Number: 66-00217-00
RT1 = THERMISTOR: Part Number: 90-00003-00
RV1 = VARISTOR: Part Number: 85-00034-00
SG1-SG4 = SPARK_GAP: Part Number: 66-00360-00
U1 = CAPZero: Part Number: 10-01229-00
U2 = HIPERPFS-3-eSIP-16C: ALT_SYMBOLS: piiclbendesiplg_socket; FPLIST: piiclbendesiplg,piiclbendesiplg_socket; Part Number: 10-01645-00
VR10 = DIODE_ZENER: Disp_Voltage: 12 V; Part Number: 15-01691-00
C20 = CAP_NP: ALT_SYMBOLS: Unisem_RMCF0805UL; Disp_Voltage: 25 V; FPLIST: pismc0805,Unisem_RMCF0805UL; Part Number: 20-00237-00; Voltage: 25 V
C22 C23 C38 C64 = CAP_NP: ALT_SYMBOLS: pismc1206_1; Disp_Voltage: 35 V; FPLIST: pismc1206,pismc1206_1; Part Number: 20-09162-00; Voltage: 35 V
C25 C50 = CAP_NP: ALT_SYMBOLS: pinpxcaprad18x6x12p1mm040H; Disp_Voltage: 1250 V; FPLIST: pinpxcaprad18x6mm040,pinpxcaprad18x6x12p1mm040H; Part Number: 20-01698-00; Voltage: 1250 V
C27 = CAP_POL: ALT_SYMBOLS: pipolcapcyld250ls100030h; Disp_Voltage: 25 V; FPLIST: pipolcapcyld250ls100030,pipolcapcyld250ls100030h; Part Number: 20-00027-00; Voltage: 25 V
C29 C63 = CAP_NP: Disp_Voltage: 25 V; Part Number: 20-00897-00; Voltage: 25 V
C36 C37 C56 C105 = CAP_NP: Disp_Voltage: 100 V; Part Number: 20-00717-00; Voltage: 100 V
C57 C115 = CAP_NP: ALT_SYMBOLS: Unisem_RMCF0805UL; Disp_Voltage: 200 V; FPLIST: pismc0805,Unisem_RMCF0805UL; Part Number: 20-01525-00; Voltage: 200 V
C100 = CAP_NP: ALT_SYMBOLS: Unisem_RMCF0603UL; Disp_Voltage: 50 V; FPLIST: pismc0603,Unisem_RMCF0603UL; Part Number: 20-09284-00; Voltage: 50 V
D4 D9 D20-D24 = DIODE: ALT_SYMBOLS: SOD323_UL_IPC,pismsod323_1; FPLIST: pismsod323,SOD323_UL_IPC,pismsod323_1; Part Number: 15-00850-00
D5 D15 D16 = DIODE: Part Number: 15-01071-00
D6 D18 D19 = DIODE: ALT_SYMBOLS: SOD323_UL_IPC,pismsod323_1; FPLIST: pismsod323,SOD323_UL_IPC,pismsod323_13; Part Number: 15-00711-00
Q13 = PNP_BEC: Part Number: 55-00049-00
R17 R20 = R: Disp_Tol: 1%; Part Number: 05-03153-00
R18 R24 = R: ALT_SYMBOLS: Unisem_RMCF0805UL; Disp_Tol: 1%; FPLIST: pismr0805,Unisem_RMCF0805UL; Part Number: 05-00496-00
R22 = R: Disp_Power: 0.25 W; Disp_Tol: 1%; Part Number: 05-06648-00
R23 = R: Part Number: 05-01335-00
R29 = R: ALT_SYMBOLS: Unisem_RMCF0603UL; Disp_Tol: 1%; FPLIST: pismr0603,Unisem_RMCF0603UL; Part Number: 05-01222-00
R65 = R: ALT_SYMBOLS: Unisem_RMCF0603UL; Disp_Tol: 1%; FPLIST: pismr0603,Unisem_RMCF0603UL; Part Number: 05-03213-00
R77 = R: ALT_SYMBOLS: Unisem_RMCF0603UL; Disp_Tol: 1%; FPLIST: pismr0603,Unisem_RMCF0603UL; Part Number: 05-03218-00
R103 = R: ALT_SYMBOLS: Unisem_RMCF0805UL; Disp_Tol: 1%; FPLIST: pismr0805,Unisem_RMCF0805UL; Part Number: 05-00684-00
R111 R157 = R: ALT_SYMBOLS: Unisem_RMCF0805UL; Disp_Power: 0.5 W; FPLIST: pismr0805,Unisem_RMCF0805UL; Part Number: 05-06922-00
R154 = R: ALT_SYMBOLS: Unisem_RMCF0603UL; FPLIST: pismr0603,Unisem_RMCF0603UL; Part Number: 05-01721-00
R155 = R: ALT_SYMBOLS: Unisem_RMCF0603UL; FPLIST: pismr0603,Unisem_RMCF0603UL; Part Number: 05-01752-00
R156 = R: ALT_SYMBOLS: Unisem_RMCF0603UL; FPLIST: pismr0603,Unisem_RMCF0603UL; Part Number: 05-01728-00
T1 = BPQ35_35_12P_GENERIC: Part Number: 25-00919-00
U3 = HiperLCS2-HB: ALT_SYMBOLS: pi_PoweDIP_B18pNH; FPLIST: pi_PoweDIP_B18pAUNP,pi_PoweDIP_B18pNH; Part Number: 10-01545-00
U9 = OPTO_DIP: Part Number: 53-00061-00
VR5 VR11 = DIODE_ZENER: Part Number: 15-01171-00
C32 C35 = CAP_POL: Disp_Voltage: 80V; FPLIST: pipolcapclyd500ls200040,pipolcapclyd500ls2000401000lh; Part Number: 20-01312-00; Voltage: 80 V
C34 = CAP_NP: Disp_Voltage: 100 V; Part Number: 20-08687-00; Voltage: 100 V
C40 = CAP_NP: ALT_SYMBOLS: Unisem_RMCF0603UL,pismc0603_1; Disp_Voltage: 250 V; FPLIST: pismc0603,Unisem_RMCF0603UL,pismc0603_1; Part Number: 20-09058-00; Voltage: 250 V
C41 = CAP_NP: ALT_SYMBOLS: Unisem_RMCF0805UL; Disp_Voltage: 200 V; FPLIST: pismc0805,Unisem_RMCF0805UL; Part Number: 20-01604-00; Voltage: 200 V
C44 = CAP_NP: ALT_SYMBOLS: Unisem_RMCF0603UL; Disp_Voltage: 200 V; FPLIST: pismc0603,Unisem_RMCF0603UL; Part Number: 20-00529-00; Voltage: 200 V
C45 = CAP_NP: ALT_SYMBOLS: Unisem_RMCF0805UL; Disp_Voltage: 50 V; FPLIST: pismc0805,Unisem_RMCF0805UL; Part Number: 20-00904-00; Voltage: 50 V
C61 = CAP_NP: ALT_SYMBOLS: Unisem_RMCF0603UL; Disp_Voltage: 50 V; FPLIST: pismc0603,Unisem_RMCF0603UL; Part Number: 20-01025-00; Voltage: 50 V
C62 = CAP_NP: ALT_SYMBOLS: Unisem_RMCF0805UL; Disp_Voltage: 250 V; FPLIST: pismc0805,Unisem_RMCF0805UL; Part Number: 20-01013-00; Voltage: 250 V
D7 D10 = DIODE: Disp_Voltage: 1000 V; Part Number: 15-02231-00
D3 D13 D14 = DIODE: Part Number: 15-00351-00
FL1 FL2 = FlyingLead: Part Number: 35-00420-00
JP1 = JUMPER_1: Part Number: 65-00622-00
JP2 JP3 = JUMPER_1: Part Number: 65-00621-00
L4 = 7448027001_L4: Case/Size Code: Type S; Category: Common Mode Chokes; ComponentLink1Description: Website Link; ComponentLink1URL: https://www.we-online.com/redexpert/article/7448027001?ad; ComponentLink2Description: Datasheet Link; ComponentLink2URL: https://www.we-online.com/redexpert/spec/7448027001?ad; CrossRef: DER 1063-ASCII-4[6C]; DC Resistance Max: 6mOhm; Height: 22mm; Insulation Test Voltage (AC): 1500V; Kind: General; Length: 18mm; Manufacturer: Wurth Elektronik; Manufacturer Part Number: 7448027001; Match Code: WE-CMBNC; Material: Nanocrystalline; Mount: Through Hole; Notes: DNP; Operating Temperature Max: 125°C; Operating Temperature Min: -40°C; Origin: Altium; Packaging: Tray; Rated Current: 7A; Rated Voltage (AC): 250V; SimulationCacheLocation: document_sim_cache\BXURYZWC\0; Spice Prefix: X; SubKind: SPICE Subcircuit; Width: 14mm
Q6 Q9 = FET_N_GDS: ALT_SYMBOLS: PI_TO220AB,PITO220ABVF1R,pidvto2203vf1h; FPLIST: PITO220ABVF1,PI_TO220AB,pidvto2203vf1h; Part Number: 50-00149-00
Q7 Q10 = FET_N_GSD: Part Number: 50-00314-00
Q11 = NPN_BEC: Part Number: 55-00030-00
R28 = R: Disp_Power: 1 W; Disp_Tol: 1%; Part Number: 05-06704-00
R31 R34 R80 = R: ALT_SYMBOLS: Unisem_RMCF0603UL; Disp_Tol: 1%; FPLIST: pismr0603,Unisem_RMCF0603UL; Part Number: 05-01225-00
R36 = R: ALT_SYMBOLS: Unisem_RMCF0603UL; Disp_Power: 0.25 W; Disp_Tol: 1%; FPLIST: pismr0603,Unisem_RMCF0603UL; Part Number: 05-06459-00
R37 R38 = R: Disp_Power: 3 W; Disp_Tol: 1%; Part Number: 05-07647-00
R40 R49 = R: ALT_SYMBOLS: Unisem_RMCF0603UL; Disp_Power: 0.125 W; Disp_Tol: 1%; FPLIST: pismr0603,Unisem_RMCF0603UL; Part Number: 05-06603-00
R41 R52 = R: ALT_SYMBOLS: Unisem_RMCF0603UL; Disp_Tol: 1%; FPLIST: pismr0603,Unisem_RMCF0603UL; Part Number: 05-01278-00
R44 R54 = R: ALT_SYMBOLS: Unisem_RMCF0603UL; Disp_Tol: 1%; FPLIST: pismr0603,Unisem_RMCF0603UL; Part Number: 05-01242-00
R46 R57 = R: ALT_SYMBOLS: Unisem_RMCF0805UL; FPLIST: pismr0805,Unisem_RMCF0805UL; Part Number: 05-01530-00
R58 = R: Disp_Power: 0.25 W; Disp_Tol: 1%; Part Number: 05-06690-00
R61 = R: ALT_SYMBOLS: Unisem_RMCF0603UL; Disp_Tol: 1%; FPLIST: pismr0603,Unisem_RMCF0603UL; Part Number: 05-01258-00
R62 = R: ALT_SYMBOLS: Unisem_RMCF0603UL; Disp_Tol: 1%; FPLIST: pismr0603,Unisem_RMCF0603UL; Part Number: 05-01256-00
R63 R131 R140 R150 = R: ALT_SYMBOLS: Unisem_RMCF0603UL; FPLIST: pismr0603,Unisem_RMCF0603UL; Part Number: 05-03158-00
R66 = R: ALT_SYMBOLS: Unisem_RMCF0603UL; Disp_Tol: 1%; FPLIST: pismr0603,Unisem_RMCF0603UL; Part Number: 05-01213-00
R27 R71 R105 = R: ALT_SYMBOLS: Unisem_RMCF0603UL; Disp_Tol: 5%; FPLIST: pismr0603,Unisem_RMCF0603UL; Part Number: 05-06645-00
R30 R72 = R: ALT_SYMBOLS: Unisem_RMCF0603UL; Disp_Power: 0.1 W; Disp_Tol: 1%; FPLIST: pismr0603,Unisem_RMCF0603UL; Part Number: 05-07609-00
R90 = R: ALT_SYMBOLS: pismr1206_1; FPLIST: pismr1206,pismr1206_1; Part Number: 05-01332-00
R104 = R: ALT_SYMBOLS: Unisem_RMCF0603UL; Disp_Tol: 1%; FPLIST: pismr0603,Unisem_RMCF0603UL; Part Number: 05-03147-00
R106-R110 = R: Part Number: 05-01389-00
RL2 = RELAY_SPST_NO_895-1A: Part Number: 66-00570-00
U6 = HiperLCS2-SR: Part Number: 10-01122-05
+60V1 GND1 = CON1_2P_TAB: Part Number: 35-00281-00
C6 = CAP_NP: ALT_SYMBOLS: pismc1206_1; Disp_Voltage: 500 V; FPLIST: pismc1206,pismc1206_1; Part Number: 20-09089-00; Voltage: 500 V
C10 C33 = CAP_NP: ALT_SYMBOLS: Unisem_RMCF0603UL,pismc0603_1; Disp_Voltage: 50 V; FPLIST: pismc0603,Unisem_RMCF0603UL,pismc0603_1; Part Number: 20-09235-00; Voltage: 50 V
C21 = CAP_POL: ALT_SYMBOLS: pipolcapclyd320ls140030430h; Disp_Voltage: 63 V; FPLIST: pipolcapclyd320ls140030,pipolcapclyd320ls140030430h; Part Number: 20-00154-00; Voltage: 63 V
C26 = CAP_POL: ALT_SYMBOLS: pipolcapclyd320ls140030430h; Disp_Voltage: 63 V; FPLIST: pipolcapclyd320ls140030,pipolcapclyd320ls140030430h; Part Number: 20-00155-00; Voltage: 63 V
C28 C54 C55 C59 C60 = CAP_NP: ALT_SYMBOLS: Unisem_RMCF0603UL; Disp_Voltage: 25 V; FPLIST: pismc0603,Unisem_RMCF0603UL; Part Number: 20-01412-00; Voltage: 25 V
C31 = CAP_NP: Disp_Voltage: 25 V; Part Number: 20-01034-00; Voltage: 25 V
C51 = CAP_NP: ALT_SYMBOLS: Unisem_RMCF0805UL; Disp_Voltage: 25 V; FPLIST: pismc0805,Unisem_RMCF0805UL; Part Number: 20-01529-00; Voltage: 25 V
C52 = CAP_NP: ALT_SYMBOLS: Unisem_RMCF0805UL; Disp_Voltage: 25 V; FPLIST: pismc0805,Unisem_RMCF0805UL; Part Number: 20-09182-00; Voltage: 25 V
C58 = CAP_NP: ALT_SYMBOLS: Unisem_RMCF0603UL; Disp_Voltage: 50 V; FPLIST: pismc0603,Unisem_RMCF0603UL; Part Number: 20-08677-00; Voltage: 50 V
J10 = HEADER10x1F: Part Number: 35-00515-00
Q12 = FET_N_SGD_123_4_5678: FPLIST: pismpqfn5x6b,TRANS_AON6407; Part Number: 50-00275-00
R3 R25 = R: Part Number: 05-01404-00
R26 = R: Part Number: 05-01328-00
R32 = R: ALT_SYMBOLS: Unisem_RMCF0603UL; FPLIST: pismr0603,Unisem_RMCF0603UL; Part Number: 05-01675-00
R35 = R: Disp_Tol: 1%; Part Number: 05-03156-00
R42 = R: ALT_SYMBOLS: Unisem_RMCF0603UL; Disp_Tol: 5%; FPLIST: pismr0603,Unisem_RMCF0603UL; Part Number: 05-06657-00
R43 = R: ALT_SYMBOLS: Unisem_RMCF0603UL; Disp_Tol: 1%; FPLIST: pismr0603,Unisem_RMCF0603UL; Part Number: 05-03188-00
R45 R47 R85 R87 R152 R153 = R: ALT_SYMBOLS: Unisem_RMCF0603UL; Disp_Tol: 1%; FPLIST: pismr0603,Unisem_RMCF0603UL; Part Number: 05-03189-00
R51 = R: Disp_Tol: 1%; Part Number: 05-05563-00
R55 = R: ALT_SYMBOLS: Unisem_RMCF0603UL; FPLIST: pismr0603,Unisem_RMCF0603UL; Part Number: 05-01664-00
R74 = R: Part Number: 05-01368-00
R75 = R: Disp_Tol: 1%; Part Number: 05-00210-00
R82 = R: ALT_SYMBOLS: Unisem_RMCF0603UL; FPLIST: pismr0603,Unisem_RMCF0603UL; Part Number: 05-01632-00
R126 R127 = R: ALT_SYMBOLS: Unisem_RMCF0603UL; Disp_Tol: 1%; FPLIST: pismr0603,Unisem_RMCF0603UL; Part Number: 05-06654-00
T2 = BEI16_10P_GENERIC: Part Number: 25-00970-00
U8 = TLV76050DBZR: Part Number: 45-01023-00
U10 = Inno3EP_P15: Part Number: 10-01104-00
VR1 VR2 = DIODE_ZENER: Part Number: 15-01093-00
C39 C114 = CAP_NP: ALT_SYMBOLS: Unisem_RMCF0603UL; Disp_Voltage: 50 V; FPLIST: pismc0603,Unisem_RMCF0603UL; Part Number: 20-01512-00; Voltage: 50 V
C42 = CAP_NP: ALT_SYMBOLS: Unisem_RMCF0805UL; Disp_Voltage: 50 V; FPLIST: pismc0805,Unisem_RMCF0805UL; Part Number: 20-00896-00; Voltage: 50 V
C43 C46 = CAP_NP: ALT_SYMBOLS: Unisem_RMCF0603UL,pismc0603_1; Disp_Voltage: 25 V; FPLIST: pismc0603,Unisem_RMCF0603UL,pismc0603_1; Part Number: 20-09147-00; Voltage: 25 V
C53 = CAP_NP: ALT_SYMBOLS: Unisem_RMCF0603UL; Disp_Voltage: 16 V; FPLIST: pismc0603,Unisem_RMCF0603UL; Part Number: 20-02217-00; Voltage: 16 V
C103 = CAP_NP: ALT_SYMBOLS: Unisem_RMCF0805UL; Disp_Voltage: 50 V; FPLIST: pismc0805,Unisem_RMCF0805UL; Part Number: 20-09227-00; Voltage: 50 V
C104 = CAP_NP: ALT_SYMBOLS: Unisem_RMCF0805UL; Disp_Voltage: 16 V; FPLIST: pismc0805,Unisem_RMCF0805UL; Part Number: 20-00676-00; Voltage: 16 V
C111 = CAP_NP: ALT_SYMBOLS: Unisem_RMCF0805UL; Disp_Voltage: 100 V; FPLIST: pismc0805,Unisem_RMCF0805UL; Part Number: 24-00030-00; Voltage: 100 V
C112 = CAP_NP: ALT_SYMBOLS: Unisem_RMCF0603UL; Disp_Voltage: 50 V; FPLIST: pismc0603,Unisem_RMCF0603UL; Part Number: 20-01051-00; Voltage: 50V
C113 = CAP_NP: ALT_SYMBOLS: Unisem_RMCF0603UL; Disp_Voltage: 50 V; FPLIST: pismc0603,Unisem_RMCF0603UL; Part Number: 20-02133-00; Voltage: 50 V
R53 = R: ALT_SYMBOLS: Unisem_RMCF0603UL; FPLIST: pismr0603,Unisem_RMCF0603UL; Part Number: 05-01699-00
R59 = R: ALT_SYMBOLS: Unisem_RMCF0805UL; Disp_Tol: 1%; FPLIST: pismr0805,Unisem_RMCF0805UL; Part Number: 05-06424-00
R60 R151 = R: ALT_SYMBOLS: Unisem_RMCF0603UL; Disp_Tol: 1%; FPLIST: pismr0603,Unisem_RMCF0603UL; Part Number: 05-03199-00
R64A R145 = POT: Part Number: 05-03518-00
R69 = R: ALT_SYMBOLS: Unisem_RMCF0805UL; Disp_Tol: 1%; FPLIST: pismr0805,Unisem_RMCF0805UL; Part Number: 05-00780-00
R70 R135 = R: ALT_SYMBOLS: Unisem_RMCF0603UL; Disp_Tol: 1%; FPLIST: pismr0603,Unisem_RMCF0603UL; Part Number: 05-07643-00
R76 = R: ALT_SYMBOLS: Unisem_RMCF0603UL; Disp_Tol: 1%; FPLIST: pismr0603,Unisem_RMCF0603UL; Part Number: 05-01191-00
R76A R133 = R: ALT_SYMBOLS: Unisem_RMCF0603UL; Disp_Tol: 1%; FPLIST: pismr0603,Unisem_RMCF0603UL; Part Number: 05-01078-00
R91 = R: ALT_SYMBOLS: Unisem_RMCF0805UL; FPLIST: pismr0805,Unisem_RMCF0805UL; Part Number: 05-01527-00
R94 R95 = R: ALT_SYMBOLS: Unisem_RMCF0805UL; FPLIST: pismr0805,Unisem_RMCF0805UL; Part Number: 05-01451-00
R96 R98 = R: ALT_SYMBOLS: Unisem_RMCF0603UL; FPLIST: pismr0603,Unisem_RMCF0603UL; Part Number: 05-01732-00
R97 = R: ALT_SYMBOLS: Unisem_RMCF0805UL; Disp_Power: 0.125 W; Disp_Tol: 5%; FPLIST: pismr0805,Unisem_RMCF0805UL; Part Number: 05-07050-00
R128 R138 = R: ALT_SYMBOLS: Unisem_RMCF0603UL; Disp_Tol: 1%; FPLIST: pismr0603,Unisem_RMCF0603UL; Part Number: 05-01174-00
R130 = R: ALT_SYMBOLS: Unisem_RMCF0603UL; Disp_Tol: 1%; FPLIST: pismr0603,Unisem_RMCF0603UL; Part Number: 05-01079-00
R132 R137 = R: ALT_SYMBOLS: Unisem_RMCF0603UL,pismr0603_1; FPLIST: pismr0603,Unisem_RMCF0603UL,pismr0603_1; Part Number: 05-01695-00
R134 = R: ALT_SYMBOLS: Unisem_RMCF0603UL; FPLIST: pismr0603,Unisem_RMCF0603UL; Part Number: 05-01696-00
R139 = R: ALT_SYMBOLS: Unisem_RMCF0603UL; Disp_Tol: 1%; FPLIST: pismr0603,Unisem_RMCF0603UL; Part Number: 05-01146-00
R141 = R: ALT_SYMBOLS: Unisem_RMCF0603UL; Disp_Tol: 1%; FPLIST: pismr0603,Unisem_RMCF0603UL; Part Number: 05-01170-00
R147 = R: ALT_SYMBOLS: Unisem_RMCF0603UL; Disp_Power: 0.1 W; Disp_Tol: 1%; FPLIST: pismr0603,Unisem_RMCF0603UL; Part Number: 05-07601-00
U4 = TL431CDBZR: Part Number: 45-00492-00
U5 = LM358: Part Number: 45-00050-00
U7 = INA180A1IDBVR: Part Number: 45-00974-00
VR7 = DIODE_ZENER: Disp_Voltage: 13 V; Part Number: 15-00710-00
VR8 = DIODE_ZENER: Part Number: 15-01089-00
HS1 = hs_0p_RD-1063: Notes: Cut length 6.37" from 61-00387-00 with 11 fins; Part Number: 61-00390-00
HS3 = hs_0p_RD-1063_RevB_LCS: Notes: Heat spreader for U3 (LCS); Part Number: 61-00391-00
HS5 = hs_0p_RD-1063_RevB_PFS: Notes: Heat spreader for U2 (PFS); Part Number: 61-00392-00
LABEL1 = Label_High_Voltage_(small): Notes: Thermal pad for U2 (PFS); Part Number: 66-00090-00
LABEL2 = Label_High_Voltage_(small): Notes: Thermal grease for U3 (LCS); Part Number: 66-00090-00
PAD1 = Thermal_PAD_RD-1063RevB: Notes: For bridge; Part Number: 61-00393-00
PAD2 = ThermPad: Notes: For U2 (PFS); Part Number: 66-00231-00
SCREW1 SCREW2 = SCR_4-40: Part Number: 75-00003-00
SCREW3 = SCR_4-40: Notes: Use for FETs and Bridge (mark in blue); Part Number: 75-00003-00
SCREW4-SCREW6 = SCR_4-40: Notes: use for all locations except FETs and Bridge; Part Number: 75-00004-00
SCREW7 SCREW9 = SCR_4-40: Part Number: 75-00004-00
SCREW8 = SCR_4-40: Notes: For stand-off; Part Number: 75-00004-00
TO-220 PAD1 = Berguist_TO-220_Pad: Notes: Use for FET Q6 & Q9; Part Number: 66-00578-00
TO-220 PAD2 = Berguist_TO-220_Pad: Notes: Use for FETs (Q6 & Q9); Part Number: 66-00578-00
WASHER1 WASHER2 = WASH_SHLDR_4: Notes: Use for FETs (Q6 & Q9); Part Number: 75-00154-00
WASHER3-WASHER9 = WASH_FLAT_4: Notes: Use for all locations except stand-off; Part Number: 75-00164-00
WASHER10 WASHER11 = WASH_LOCK_4: Notes: For stand-off; Part Number: 75-00028-00
WASHER12 WASHER13 = WASH_FLAT_4: Notes: Cut length 0.18"; Part Number: 75-00176-00

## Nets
5VL: C29.1 C45.1 D22.1(K) Q13.2(EMITTER) R65.2 R156.1 U3.7(5VL) U6.15(5VL)
5VS: C49.1 U6.1(5VS)
12V: C26.1 C46.1 D10.1(K) J10.2 R27.1 R30.1 R53.1 R75.1 R95.2 RL2.1 T2.9 U5.8(V+) U8.2 U10.6(VO)
+2.5V: C43.1 R53.2 R152.1 R153.1 U4.1(C) U4.2(VREF)
+5V: C51.1 C104.2 U7.5 U8.1
+12V_pmy: C8.1 C17.1 Q8.3 R125.1 RL1.1(COIL1) U2.1(Vcc)
GND_EARTH: C1.2 C7.1 C109.2 C110.1 E.1 MTG_HOLE1.1
AUX_PRI: C21.1 D3.1(K) D24.2(A) Q2.2 R11.1 R19.1 R74.1
BAT+: +60V1.1 JP1.2 R28.2 R31.1 RL2.4
BAT-: C105.2 GND1.1 JP3.2 L4.4 R106.2
BAT-ADC: J10.9 R31.2 R33.1
BM: D4.1(K) R4.2
BP_Relay: Q2.3 R23.2
BPP: C27.1 D5.2(A) D6.1(K) R24.2
BPS: C38.1 C63.1 D21.1(K) D23.1(K) R40.1 R49.1 R97.1 U6.7(BPS)
CS+: C107.2 JP3.1 L4.1 R37.2 R38.2 R106.1 R139.1
FB: C61.2 D9.1(K) D20.1(K) R34.2 R36.1 U6.5(FB)
FL: U3.6(FL) U6.14(FL)
GD: C24.2 C27.2 U3.10(GD)
GP: C29.2 C45.2 C100.2 R29.2 U3.4(GP) U6.16(G) U9.3(E)
GSA: C2.2 C26.2 C28.1 C30.2 C31.1 C32.2 C33.2 C35.2 C36.2 C37.2 C38.2 C43.2 C46.2 C51.2 C53.2 C54.2 C55.1 C56.2 C59.1 C60.1 C63.2 C64.2 C103.2 C104.1 C111.2 C114.2 D16.2(A) J10.1 J10.7 Q6.3(S) Q9.3(S) Q11.2(EMITTER) Q12.1(S) R33.2 R37.1 R38.1 R39.1 R43.2 R50.1 R64A.3(CW) R69.1 R72.2 R75.2 R76.1 R81.2 R82.2 R108.2 R109.2 R110.2 R126.1 R130.2 R134.1 R138.1 R140.1 R145.3(CW) U4.3(A) U5.4(V-) U6.12(GSA) U7.2 U8.3 U9.2(C) U10.1(IS) U10.2(G) VR7.2 VR8.2
GSB: C34.2 C40.2 C41.2 C49.2 C57.2 C61.1 C115.2 R36.2 R66.2 R103.2 R104.2 T1.11 U6.2(GSB)
IOUT: R105.1 R137.2 R141.2 U7.1
IOUT-ADC: J10.8 R105.2
IS: C44.1 C57.1 C102.2 R103.1 R111.2
MCU_IPWM: C59.2 R47.2 R85.1
MCU_Relay: J10.6 R71.1
MCU_VPWM: C60.2 R68.2 R87.1
NC: U2.14(NC)
NC8: U10.8(NC8)
NC9: U10.9(NC9)
NC10: U10.10(NC10)
NC11: U10.11(NC11)
NC12: U10.12(NC12)
ON: D19.2(A) J10.3
OUT+: C32.1 C34.1 C35.1 C36.1 C37.1 C62.2 C106.1 C111.1 D18.2(A) JP2.1 L4.2 R34.1 R80.1 R94.1 R98.2 R107.1 R108.1 R109.1 R110.1 R131.1 T1.7 T1.8 T1.9 VR11.2
OUT++: C105.1 D7.2(A) JP1.1 JP2.2 L4.3 R107.2 RL2.2
PG_PFS: R77.1 U2.8(PG)
RefCC: C54.1 R47.1 R64A.2(WIPER) R138.2 R151.1 R152.2
RTN: BR1.4(-DC) C3.2 C8.2 C9.2 C9A.2 C9B.2 C11.2 C21.2 C25.2 C30.1 C52.2 L3.4 Q1.2(S) R5.2 R74.2 T1.5 T2.2 U2.10(S1) U3.11(S) U10.16(S) VR2.2 VR10.2
SOURCE: U2.11(SOURCE)
VBULK: C2.1 C6.1 C9.1 C9A.1 C9B.1 C11.1 C50.1 D2.1(K) R3.1 R6.1 R17.1 R25.1 R35.1 T2.3 U2.16(K) U3.20(HD)
VOUT-ADC: J10.10 R80.2 R81.1
VRECT: BR1.1(+DC) C3.1 D2.2(A) L3.2 R8.2
N13075197: F1.1 L.1
N13075201: C1.1 F1.2 RL1.4(NO) RT1.1 RV1.1
N13075229: C108.1 L5.1 R118.1 RL1.3(COMMON) RT1.2 SG1.1
N13075257: C4.1 C109.1 L1.1 L5.4 R101.1 R118.2 SG1.2 SG3.1
N13075293: BR1.2(AC1) C5.1 L1.4 R1.1 R101.2 SG3.2
N13075321: BR1.3(AC2) L2.2
N13075467: R1.2 U1.1(NC1) U1.2(D1) U1.3(NC2) U1.4(NC3)
N13075621: C7.2 C108.2 L5.2 N.1 R119.1 RV1.2 SG2.1
N13075629: C4.2 C110.2 L1.2 L5.3 R102.1 R119.2 SG2.2 SG4.1
N13075705: C5.2 L1.3 L2.1 R2.2 R102.2 SG4.2
N13075741: R2.1 U1.5(NC4) U1.6(NC5) U1.7(D2) U1.8(NC8)
N13076159: D1.2(A) Q1.3(D) RL1.2(COIL2)
N13076167: D1.1(K) R125.2
N13076321: Q1.1(G) R4.1 R5.1
N13076547: R8.1 R9.2
N13076615: L3.8 U2.13(D)
N13076627: R6.2 R7.1
N13076649: C18.1 R14.2 R16.1 U2.7(FB)
N13076657: C13.1 R12.1 U2.9(PGT)
N13076673: R9.1 R10.1
N13076695: C12.1 R13.1 U2.6(C)
N13076727: C15.1 R10.2 R15.1 U2.5(V)
N13076745: R7.2 R14.1
N13076899: C12.2 C13.2 C14.2 C15.2 C16.2 C17.2 C18.2 R12.2 R15.2 R16.2 U2.4(G)
N13076903: C14.1 U2.3(REF)
N13077057: C16.1 R13.2
N13077081: Q8.2 R11.2 R89.1
N13077159: Q8.1 R89.2 VR10.1
N13081652: C19.1 R18.1 U3.13(BPH)
N13081672: R17.2 R20.1
N13081712: C19.2 C20.2 C22.2 C23.2 T1.2 U3.15(HB)
N13081716: C22.1 C23.1 R18.2 R21.2
N13081774: C20.1 U3.14(5VH)
N13081802: C25.1 C50.2 T1.1
N13081806: R20.2 R22.1
N13081894: D5.1(K) R21.1
N13081936: C100.1 D22.2(A) R22.2 R65.1 R77.2 R154.1 U3.2(L)
N13081966: C102.1 C115.1 R111.1 R157.2
N13082106: R157.1 T1.12
N13082142: D4.2(A) U3.9(BM)
N13082252: R29.1 U3.5(PP)
N13082394: C24.1 R24.1 U3.8(BP)
N13082422: D6.2(A) R23.1
N13082998: R79.1 R88.1 U9.1(A)
N13083006: D19.1(K) R88.2
N13083046: R155.1 R156.2 U9.4(Collector)
N13083116: R79.2 VR5.2
N13083120: C56.1 D18.1(K) VR5.1
N13129300: D13.2(A) FL1.1 Q9.2(D) Q10.3(D)
N13129338: C106.2 C107.1 MTG_HOLE5.1
N13129680: R90.2 VR11.1
N13129962: D14.2(A) FL2.1 Q6.2(D) Q7.3(D)
N13130082: Q6.1(G) R39.2 R41.1
N13130158: Q7.1(G) R40.2 R44.1
N13130170: Q7.2(S) R44.2 R46.1
N13130230: R41.2 U6.8(G2)
N13130322: R46.2 U6.10(D2)
N13130482: Q9.1(G) R50.2 R52.1
N13130510: C40.1 R58.1 R104.1 U6.4(CMP)
N13130530: Q10.1(G) R49.2 R54.1
N13130550: Q10.2(S) R54.2 R57.1
N13130620: R52.2 U6.9(G1)
N13130700: C41.1 R58.2
N13130736: R57.2 U6.11(D1)
N13130824: R61.1 U6.3(IS)
N13130832: R61.2 R62.1
N13130836: R62.2 R63.1
N13130840: C44.2 R63.2
N13131010: R66.1 U6.6(PS)
N13134664: C28.2 R42.1 R85.2
N13134676: J10.4 R42.2
N13134874: C55.2 R45.1 R87.2
N13134886: J10.5 R45.2
N13135254: R35.2 R51.1
N13135258: C6.2 R3.2 R25.2 R26.1
N13135288: C58.1 D16.1(K) Q12.5(D) R32.1 T2.7
N13135376: D15.1(K) R26.2
N13135380: D15.2(A) T2.5 U10.24(D)
N13135402: Q12.4(G) R127.1
N13135462: R126.2 R127.2 U10.5(SR)
N13135530: D3.2(A) T2.1
N13135582: Q2.1 R19.2 VR2.1
N13135930: C58.2 R82.1
N13136072: C10.1 R27.2
N13136170: C10.2 C33.1 R30.2 R43.1 U10.3(FB)
N13136174: D24.1(K) R55.1 R84.2
N13136212: R32.2 U10.7(FW)
N13136306: C31.2 U10.4(BPS)
N13136428: R55.2 VR1.1
N13136440: C52.1 R84.1 U10.14(BPP) VR1.2
N13140087: R51.2 U10.13(VPIN)
N13191912: C39.1 R59.2 R151.2 U5.2(-IN)
N13191920: C39.2 C42.1 R147.1 U5.1(OUT)
N13192176: C42.2 R59.1
N13192240: C103.1 R139.2 U7.3
N13192354: D9.2(A) R60.1
N13192496: R137.1 U5.3(+IN)
N13192500: R140.2 R141.1 U7.4
N13192960: R128.1 R131.2
N13193004: R128.2 R130.1 R132.1
N13193032: R76A.1 R132.2 U5.5(+IN)
N13193186: C53.1 R68.1 R76.2 R76A.2
N13193272: C112.2 C113.1 R91.2 R135.2 U5.7(OUT)
N13193284: R91.1 R133.2 R134.2
N13193324: C113.2 R69.2 R70.2 R150.2 U5.6(-IN)
N13193524: C112.1 R70.1 R135.1
N13193682: R145.2(WIPER) R150.1 R153.2
N13193934: Q3.2 R94.2 R96.1
N13193966: D21.2(A) Q3.3
N13193994: D23.2(A) Q5.3
N13194018: Q5.2 R95.1
N13194026: Q3.1 R96.2 VR8.1
N13194030: Q5.1 R98.1 VR7.1
N13194134: C64.1 R97.2
N13204238: D20.2(A) R133.1
N13219296: C114.1 R60.2 R147.2
N13249684: D7.1(K) R28.1
N13249824: D10.2(A) Q11.3(COLLECTOR) RL2.3
N13249932: Q11.1(BASE) R71.2 R72.1
N13259403: C62.1 D13.1(K) D14.1(K) R90.1
N13332978: Q13.1(BASE) R155.2
N13335649: Q13.3(COLLECTOR) R154.2

Not connected (* = marked no-connect by the designer): +60V1 2; E 2; GND1 2; L 2; L3 1 3 5 6 7 9 10 11 12; MTG_HOLE2 1; MTG_HOLE3 1; MTG_HOLE4 1; MTG_HOLE6 1; MTG_HOLE7 1; N 2; Q2 4; Q3 4; Q5 4; Q8 4; Q12 2(S2) 3(S3) 6(D6) 7(D7) 8(D8); R64A 1(CCW); R145 1(CCW); T1 3 4 6 10; T2 4 6 8 10; U6 13(NC13) 24(NC24); U10 15(nc15)

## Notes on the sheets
sheet 2
- DNP
- DNP
- CC LOOP
- DNP
- DNP
- DNP
- DNP
- CV LOOP
- DNP
- DNP
- DNP
- DNP
- DNP
- DNP
- BPS capacitor
- DNP
- Vout regulator
- Aux regulator
- DNP
- DNP
- DNP
- DNP
- 720W LCS2 CVCC Controller
sheet 3
- DNP
- DNP
- DNP
- DNP
- DNP
- DNP
- 720W LCS2 AUXILIARY
sheet 4
- DNP
- DNP
- DNP
- DNP
- DNP
- DNP
- DNP
- DNP
- DNP
- DNP
- DNP
- DNP
- 720W LCS2 SECONDARY
sheet 5
- DNP
- DNP
- DNP
- DNP
- DNP
- 720W LCS2 PRIMARY
sheet 6
- AC Input
  180-270 VAC
- 720W LCS2 EMI + PFC
